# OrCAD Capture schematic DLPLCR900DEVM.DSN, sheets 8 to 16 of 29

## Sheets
8 P23-DMD Flex Connector: size A3
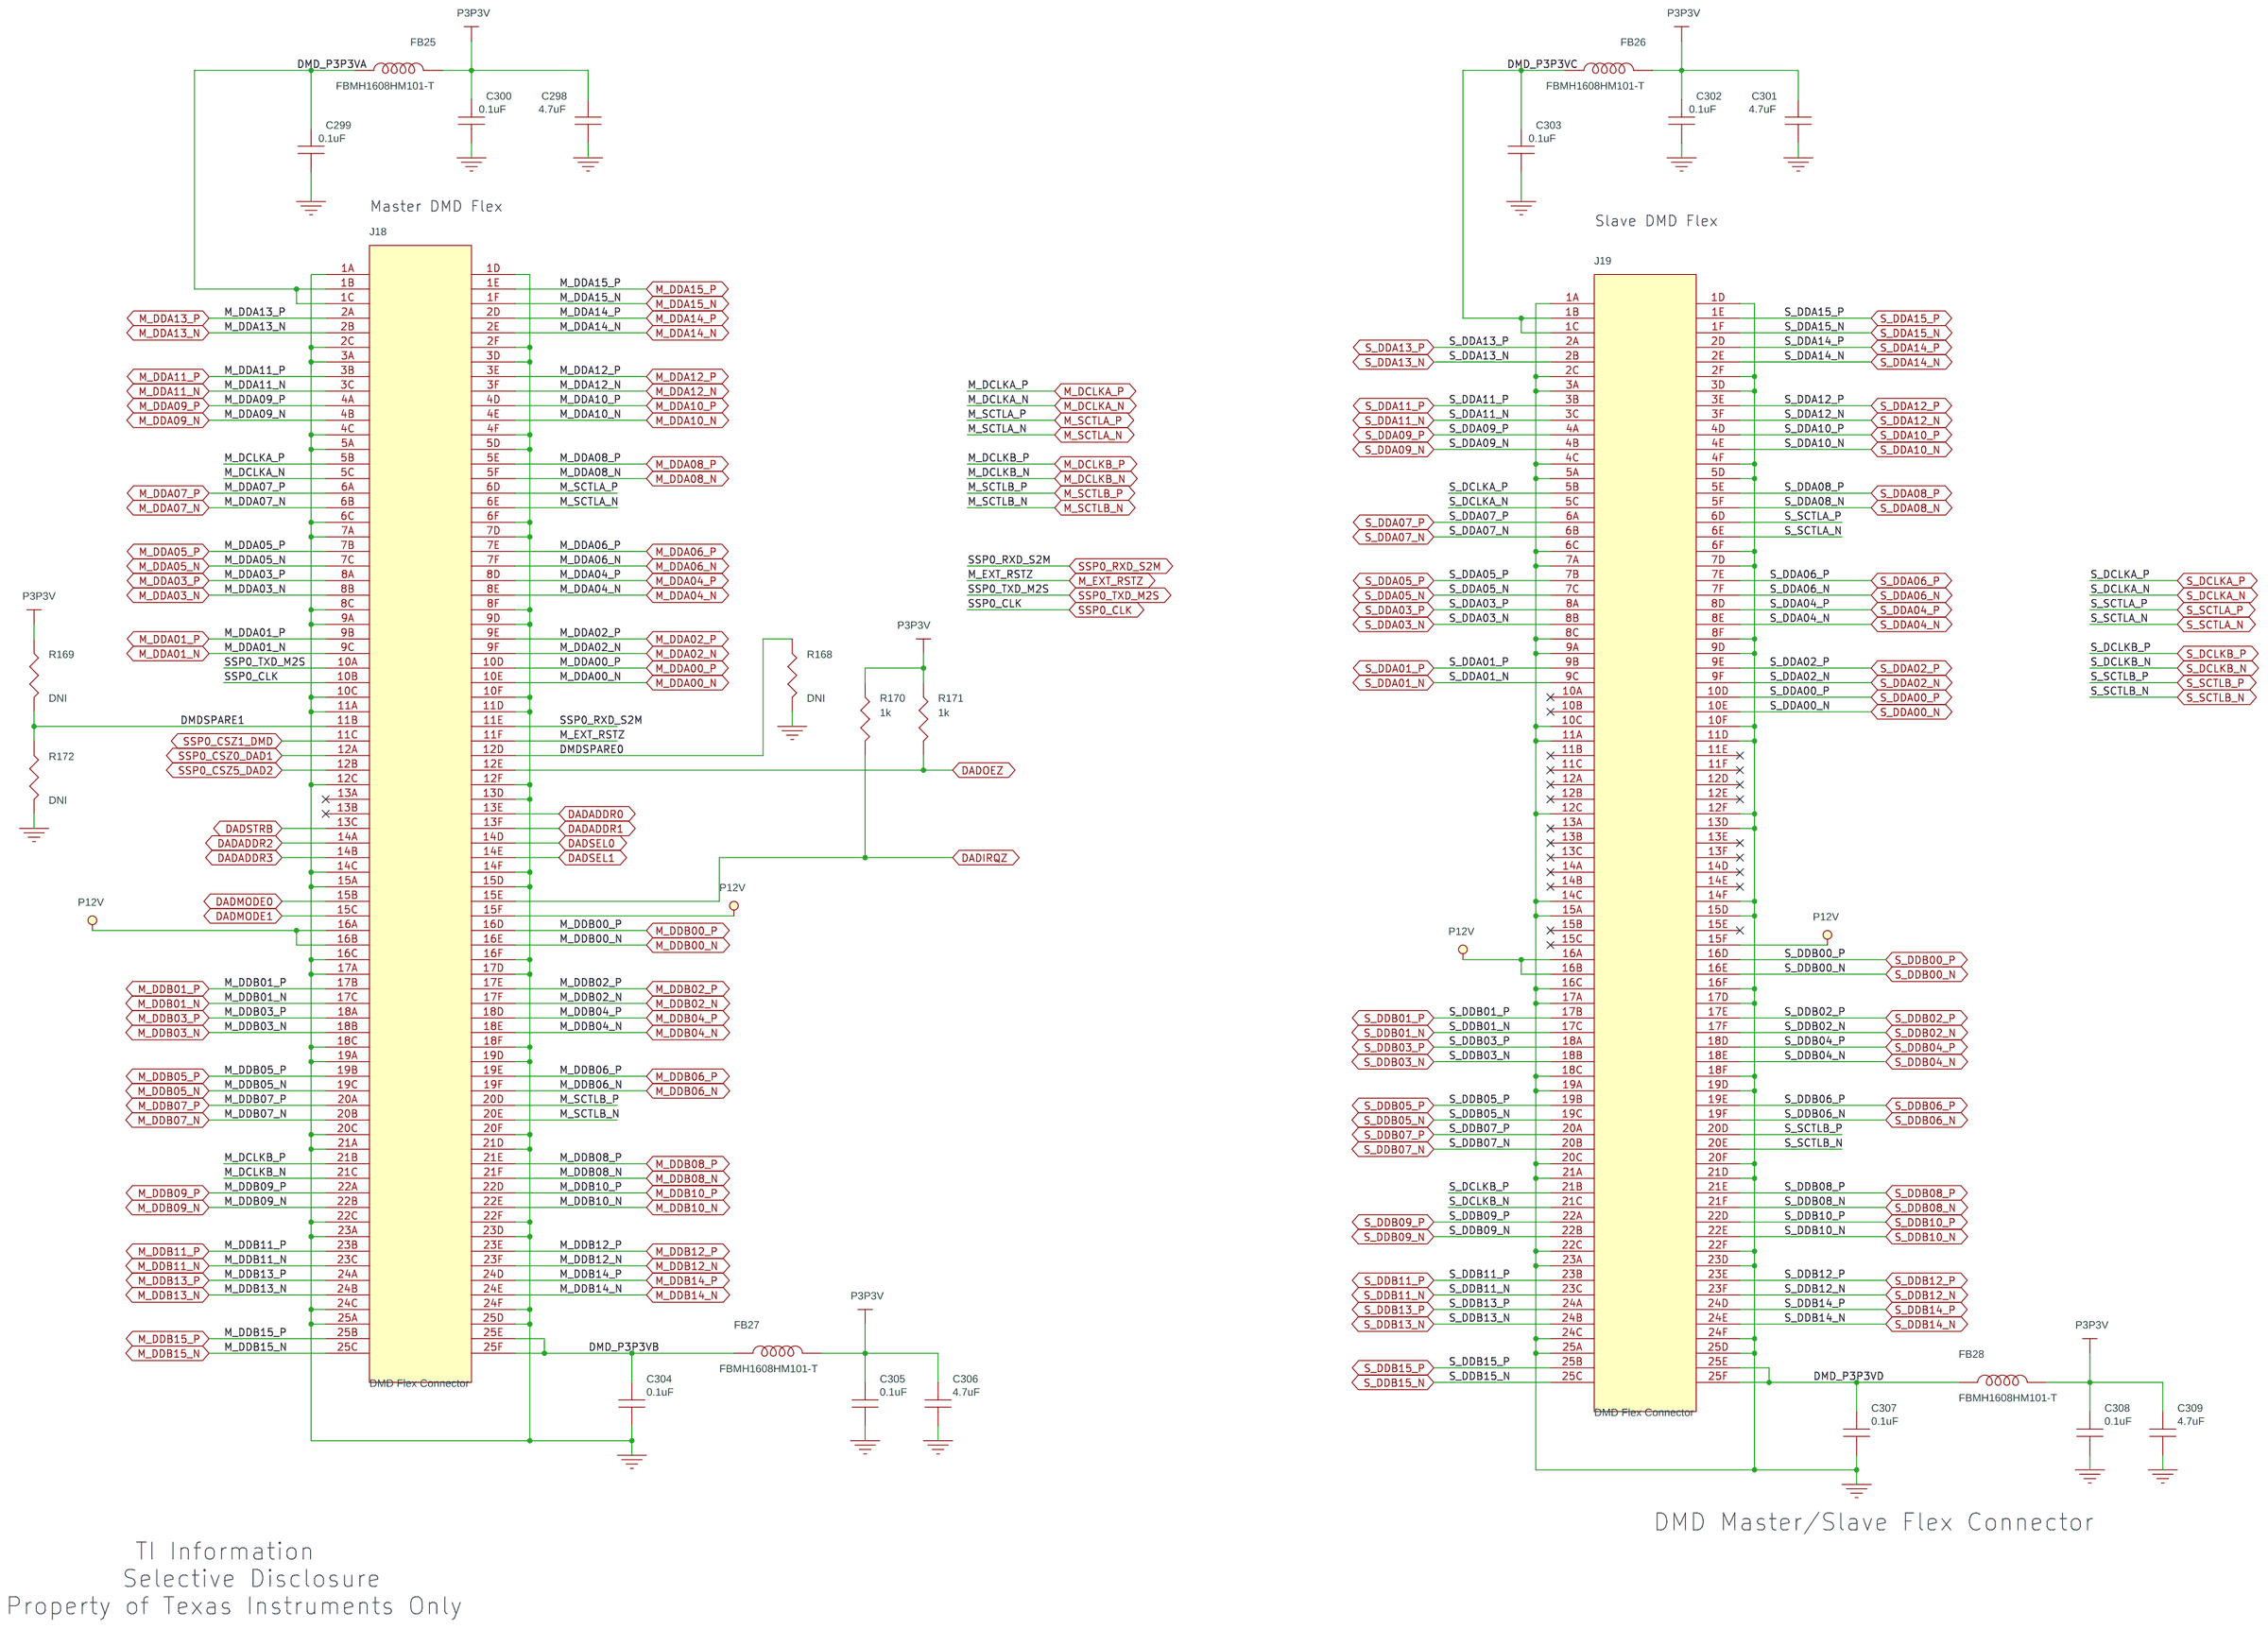
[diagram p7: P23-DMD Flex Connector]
9 P20-Slave Ext Flash Intf: size A3
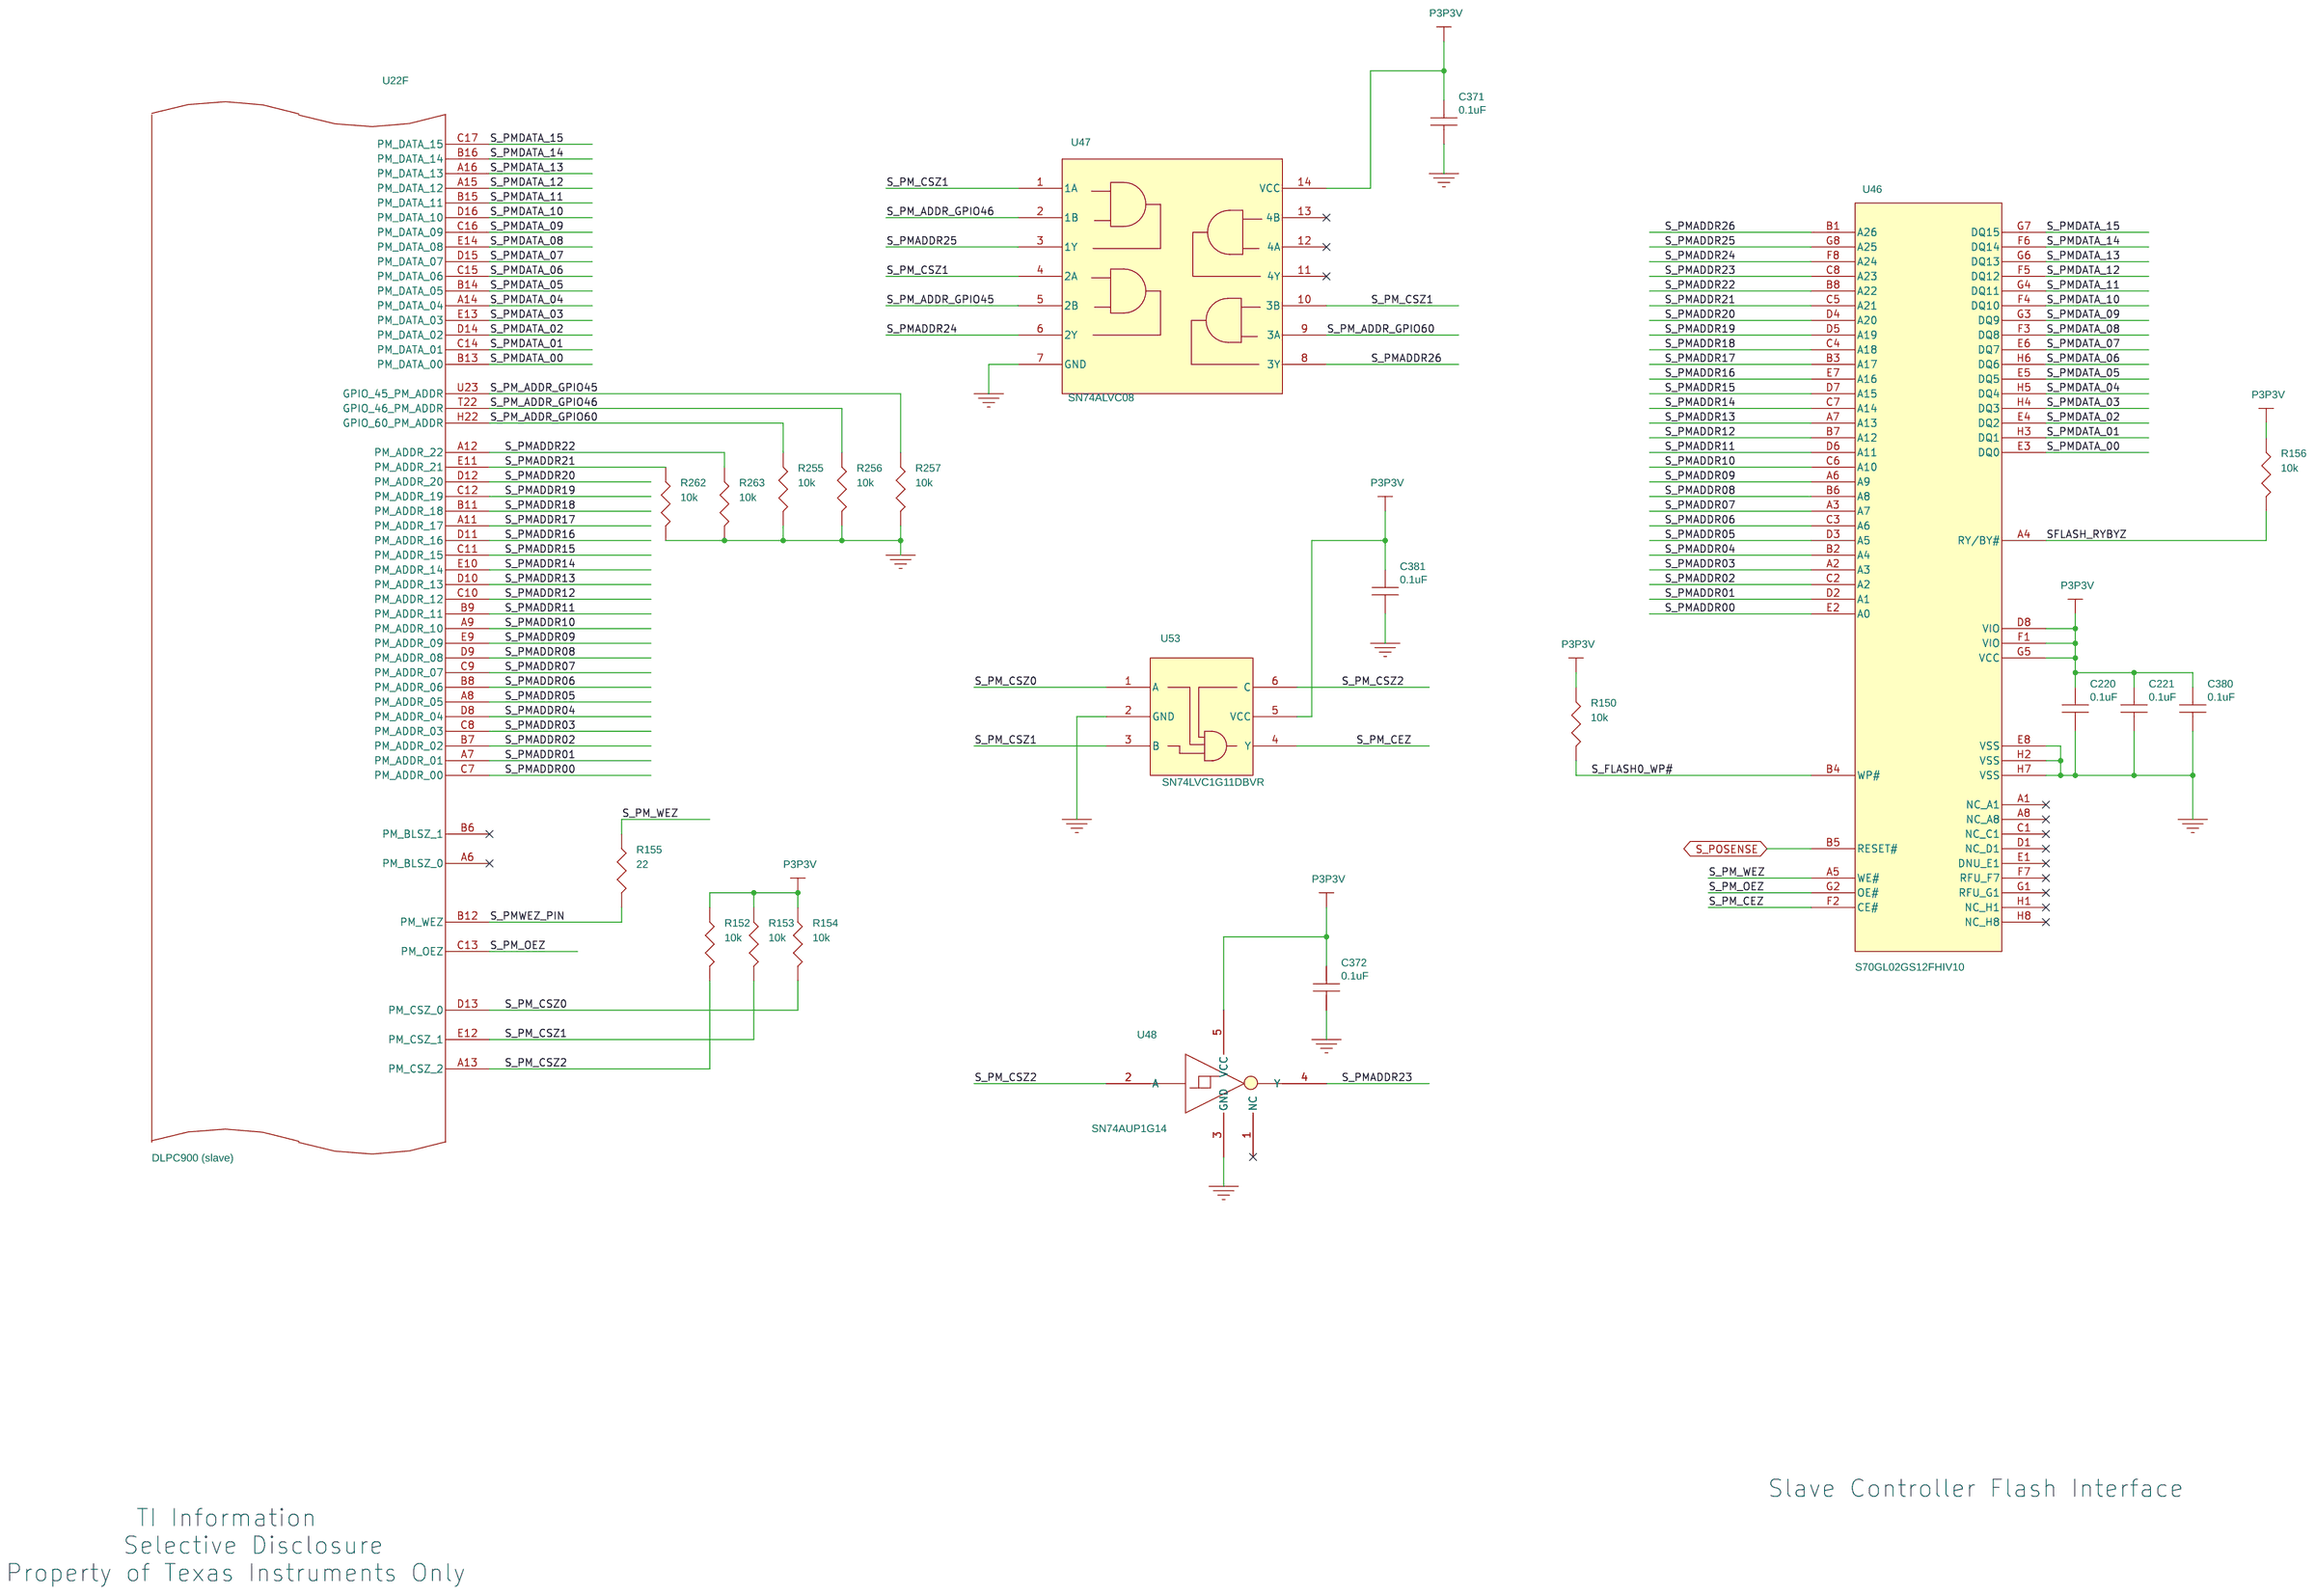
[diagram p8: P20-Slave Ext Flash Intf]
10 P21-Slave GPIOs: size A3
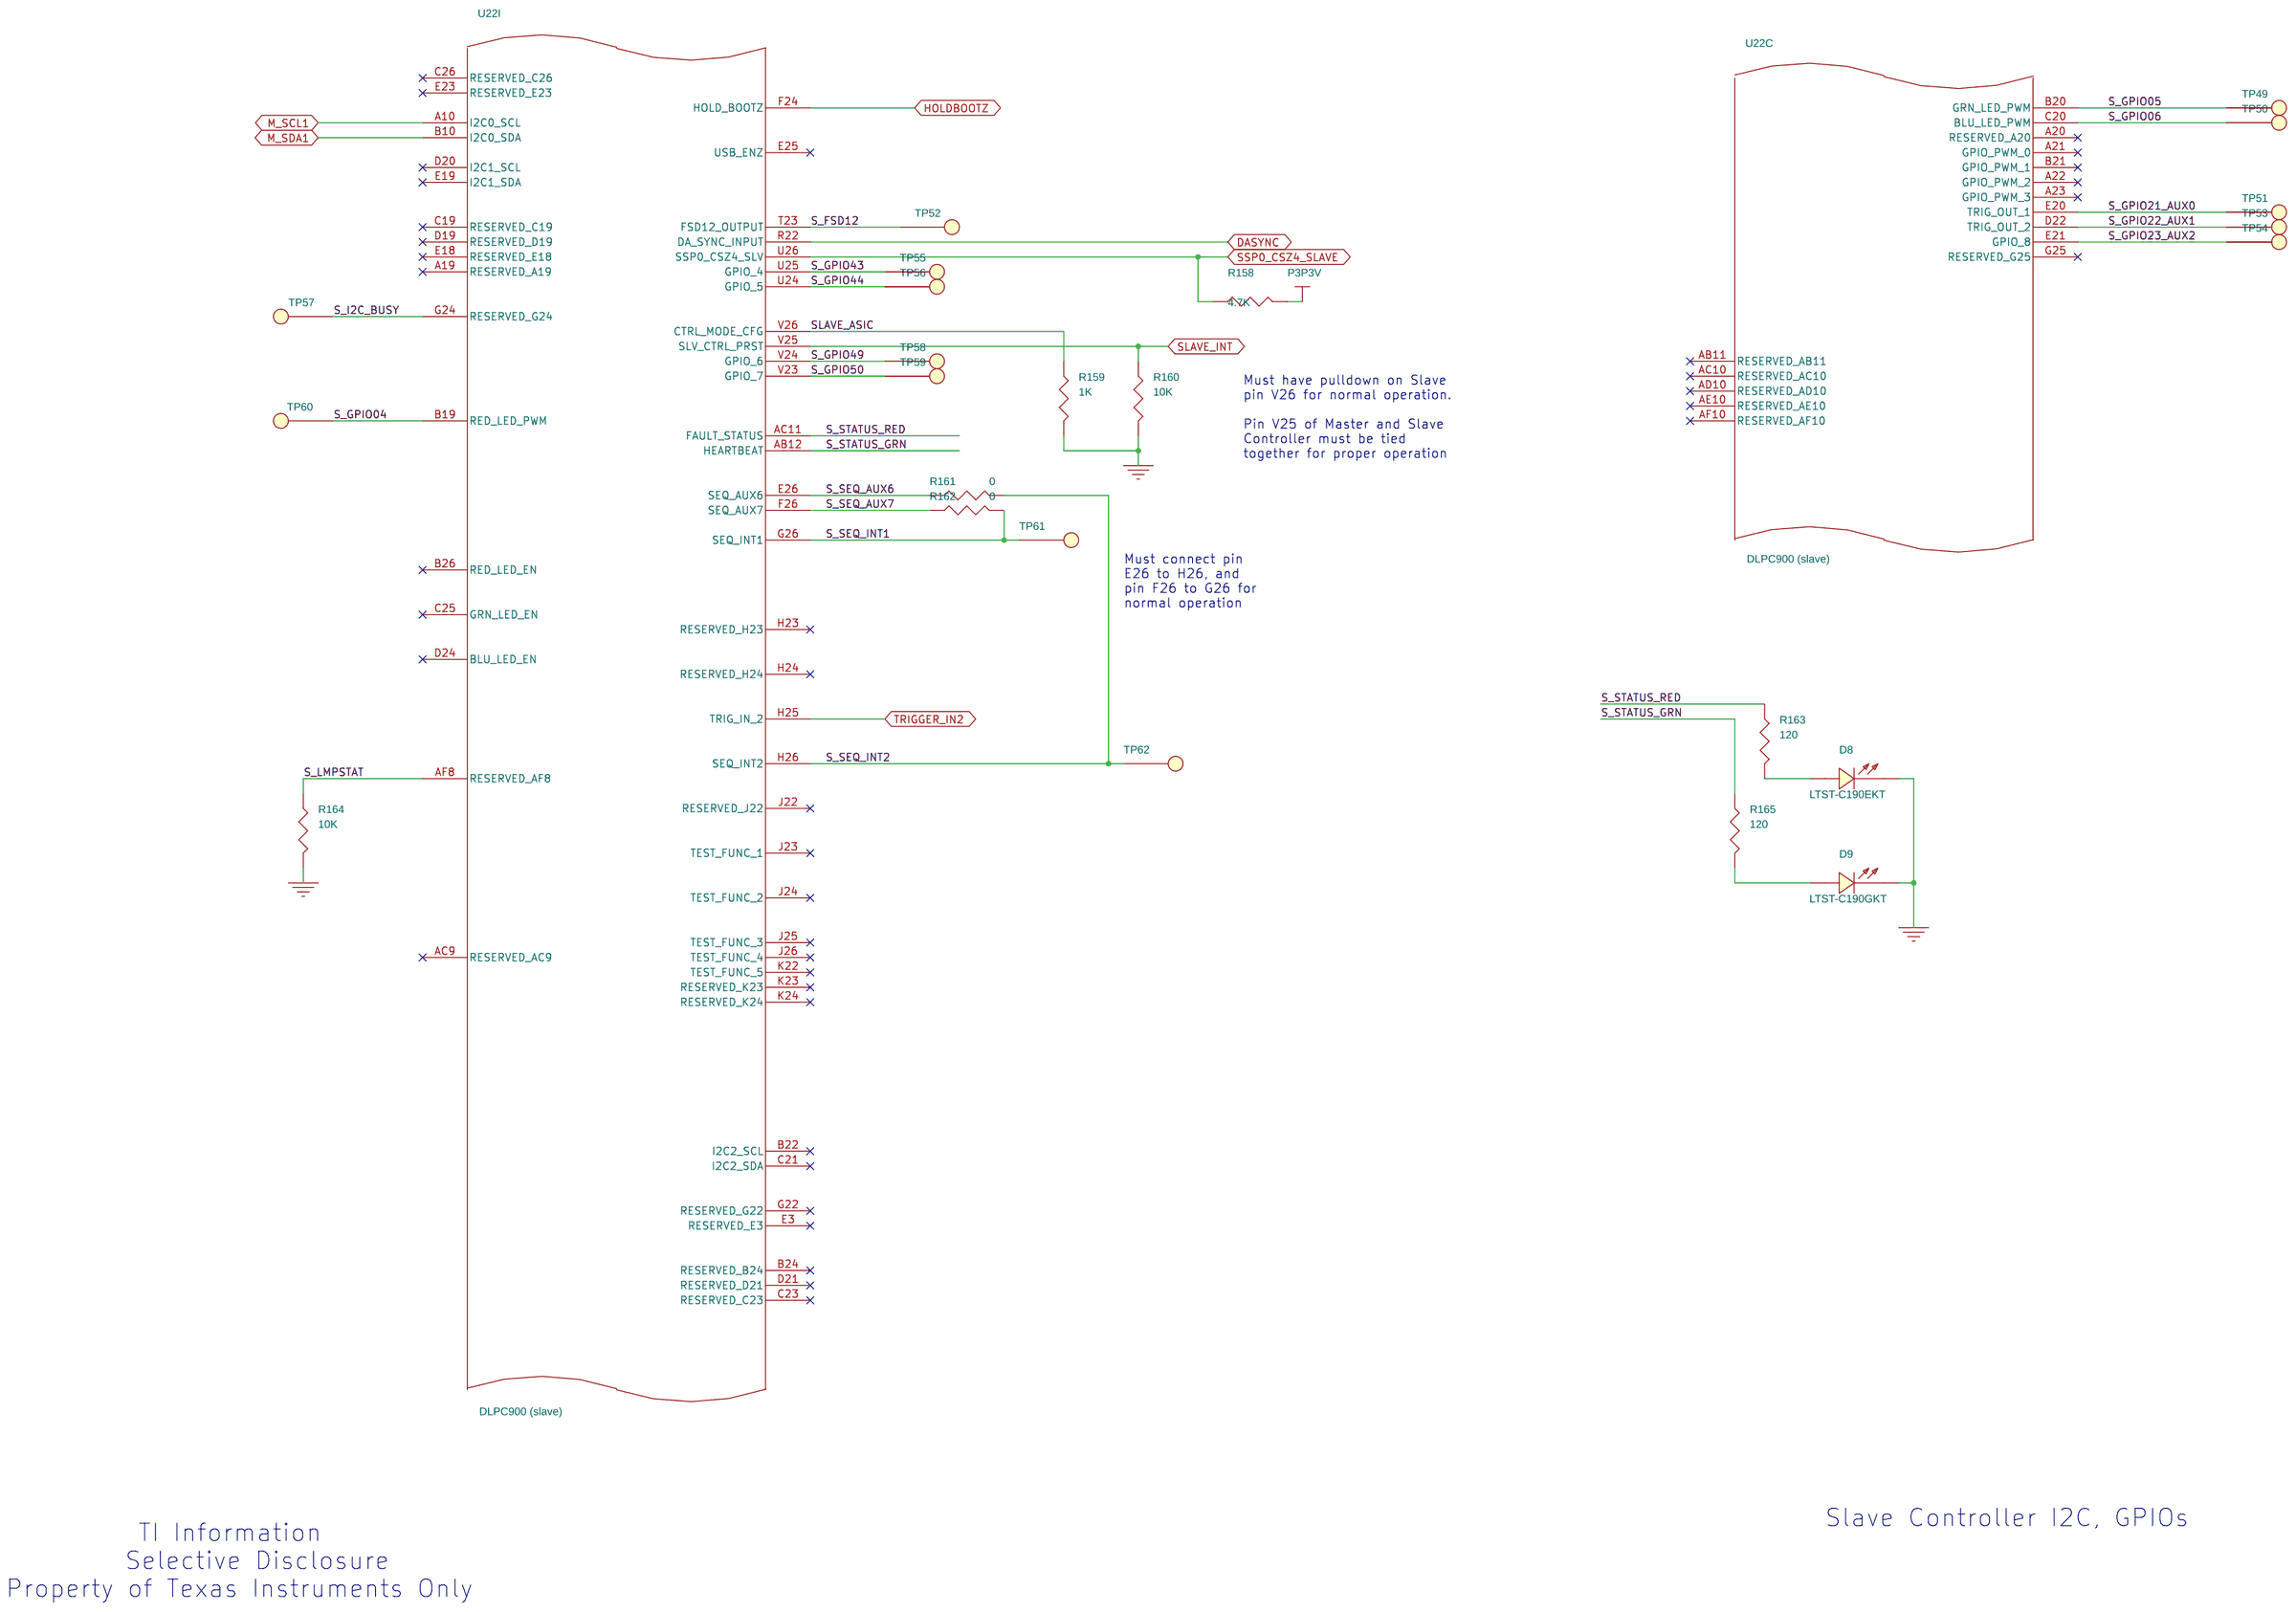
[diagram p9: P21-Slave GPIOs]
11 P19-Slave JTAG Osc Rst SSP: size A3
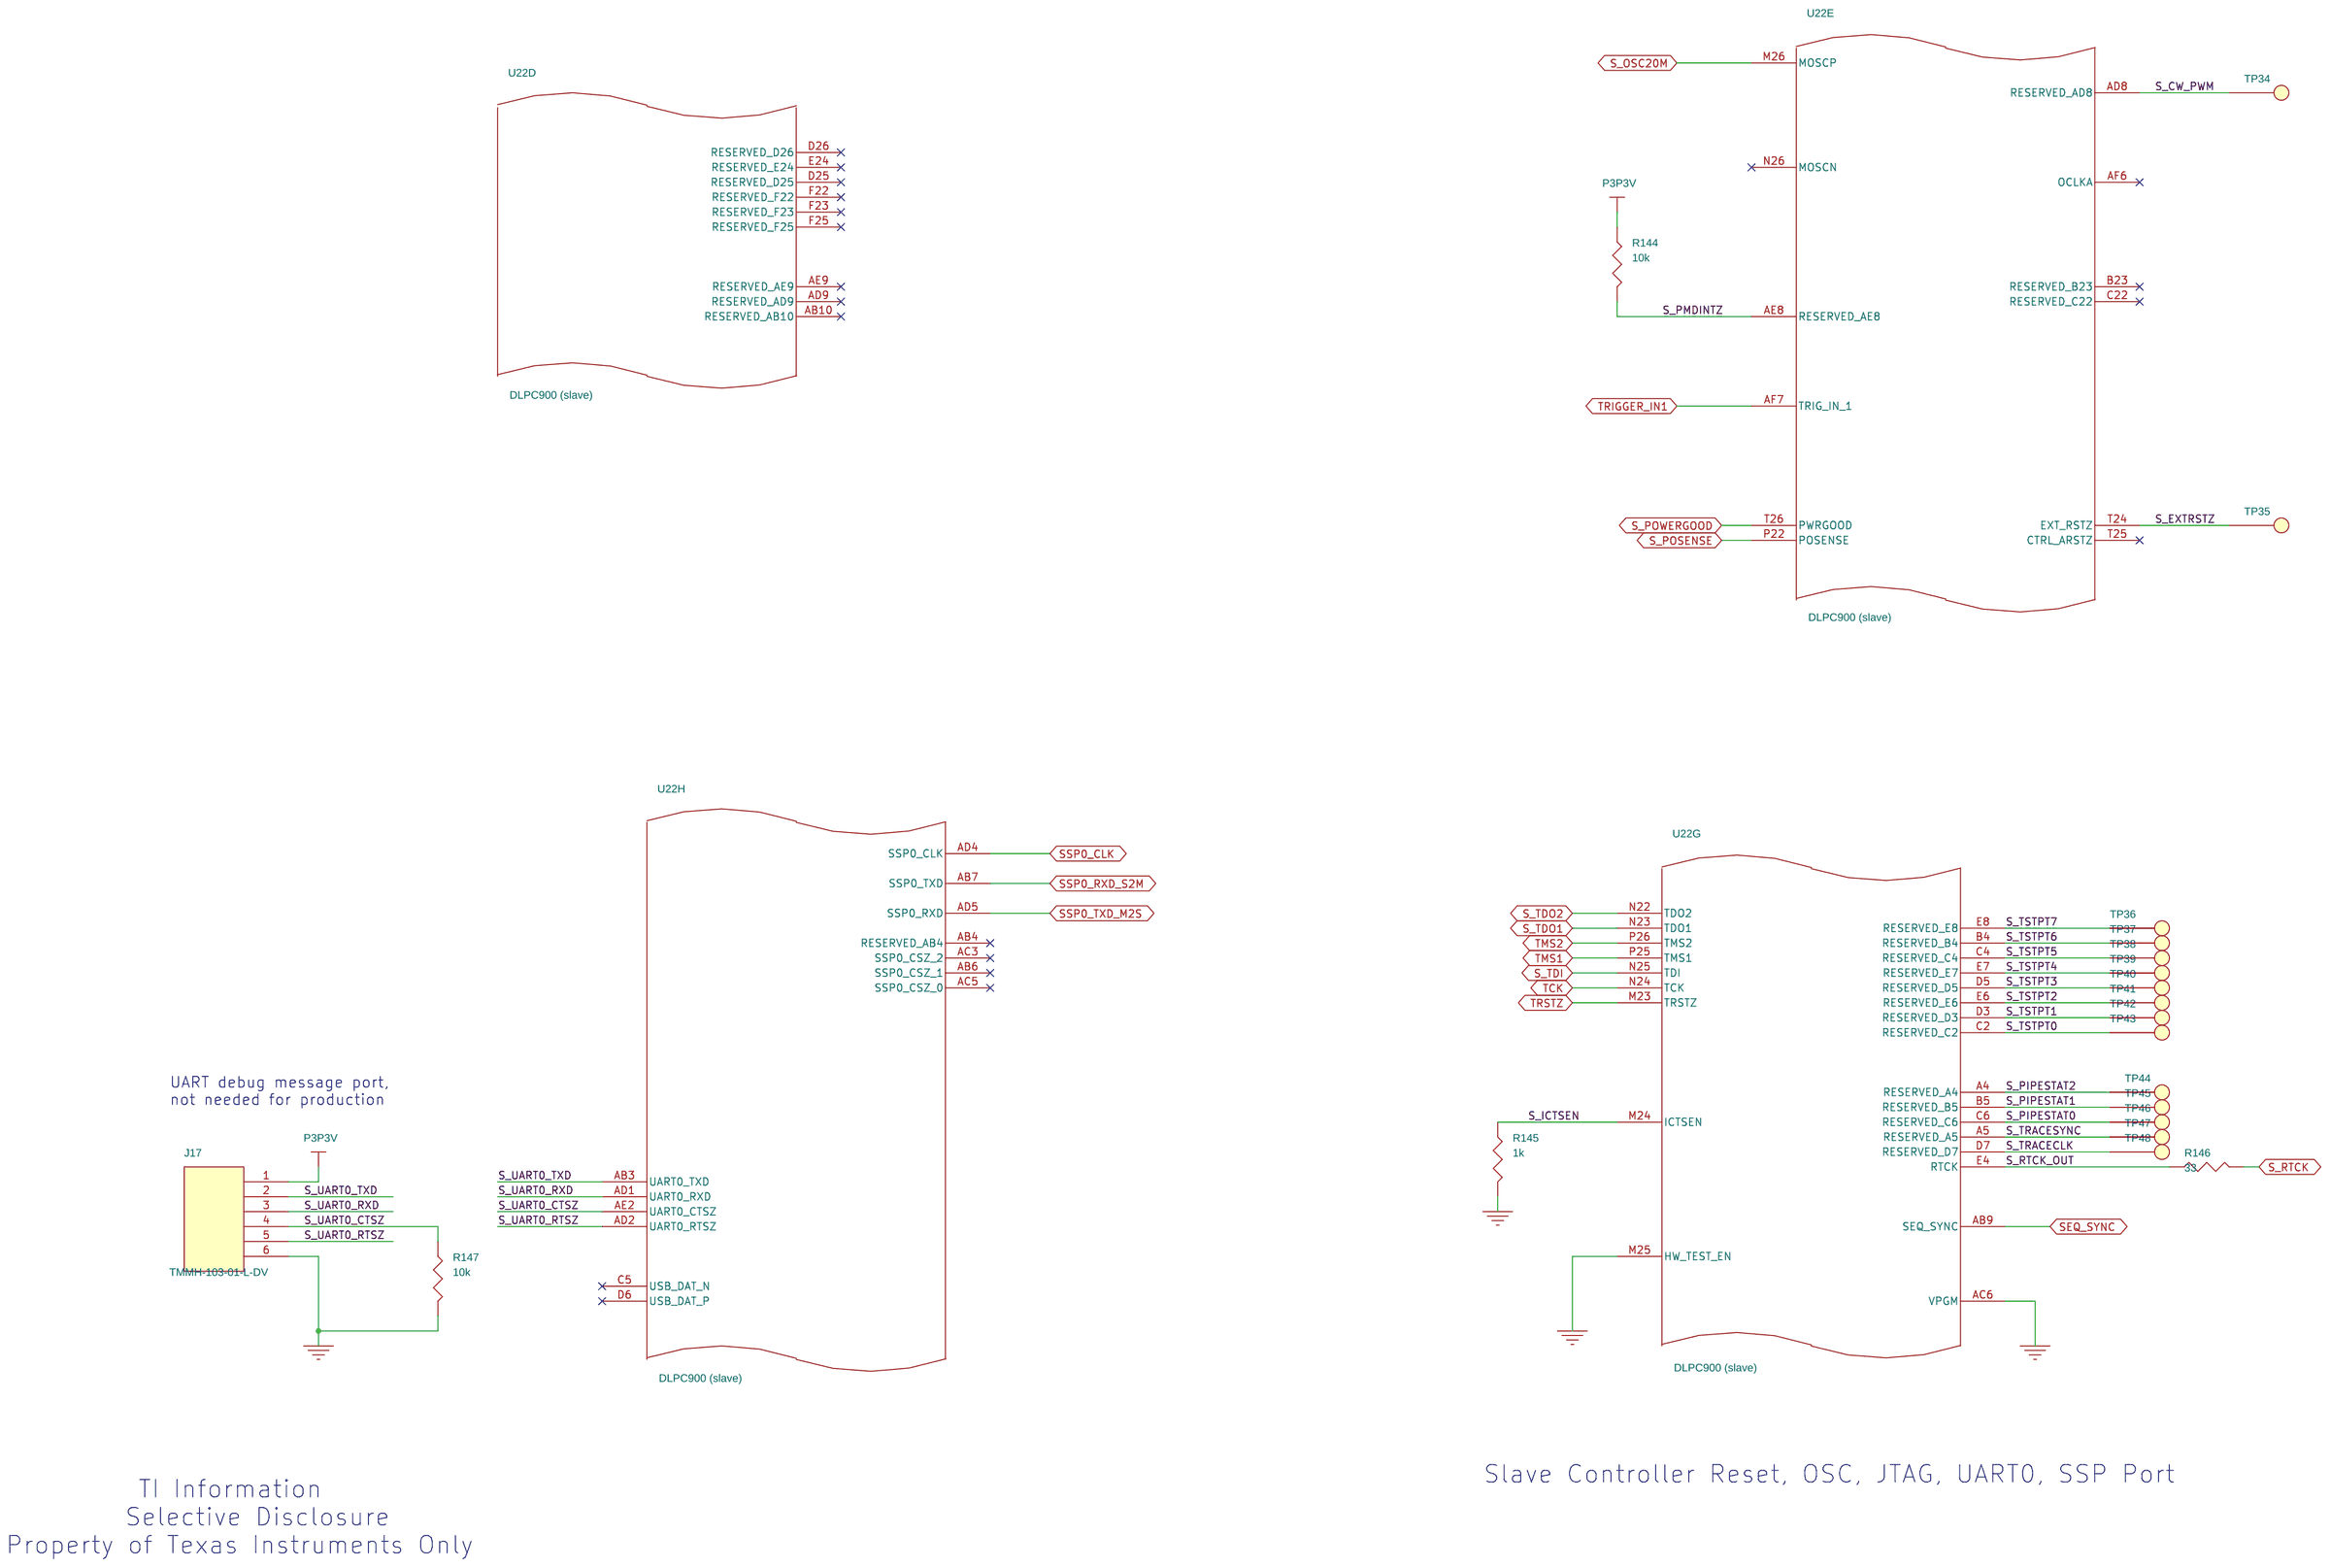
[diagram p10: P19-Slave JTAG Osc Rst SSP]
12 P18-Slave Vid DMD io: size A3
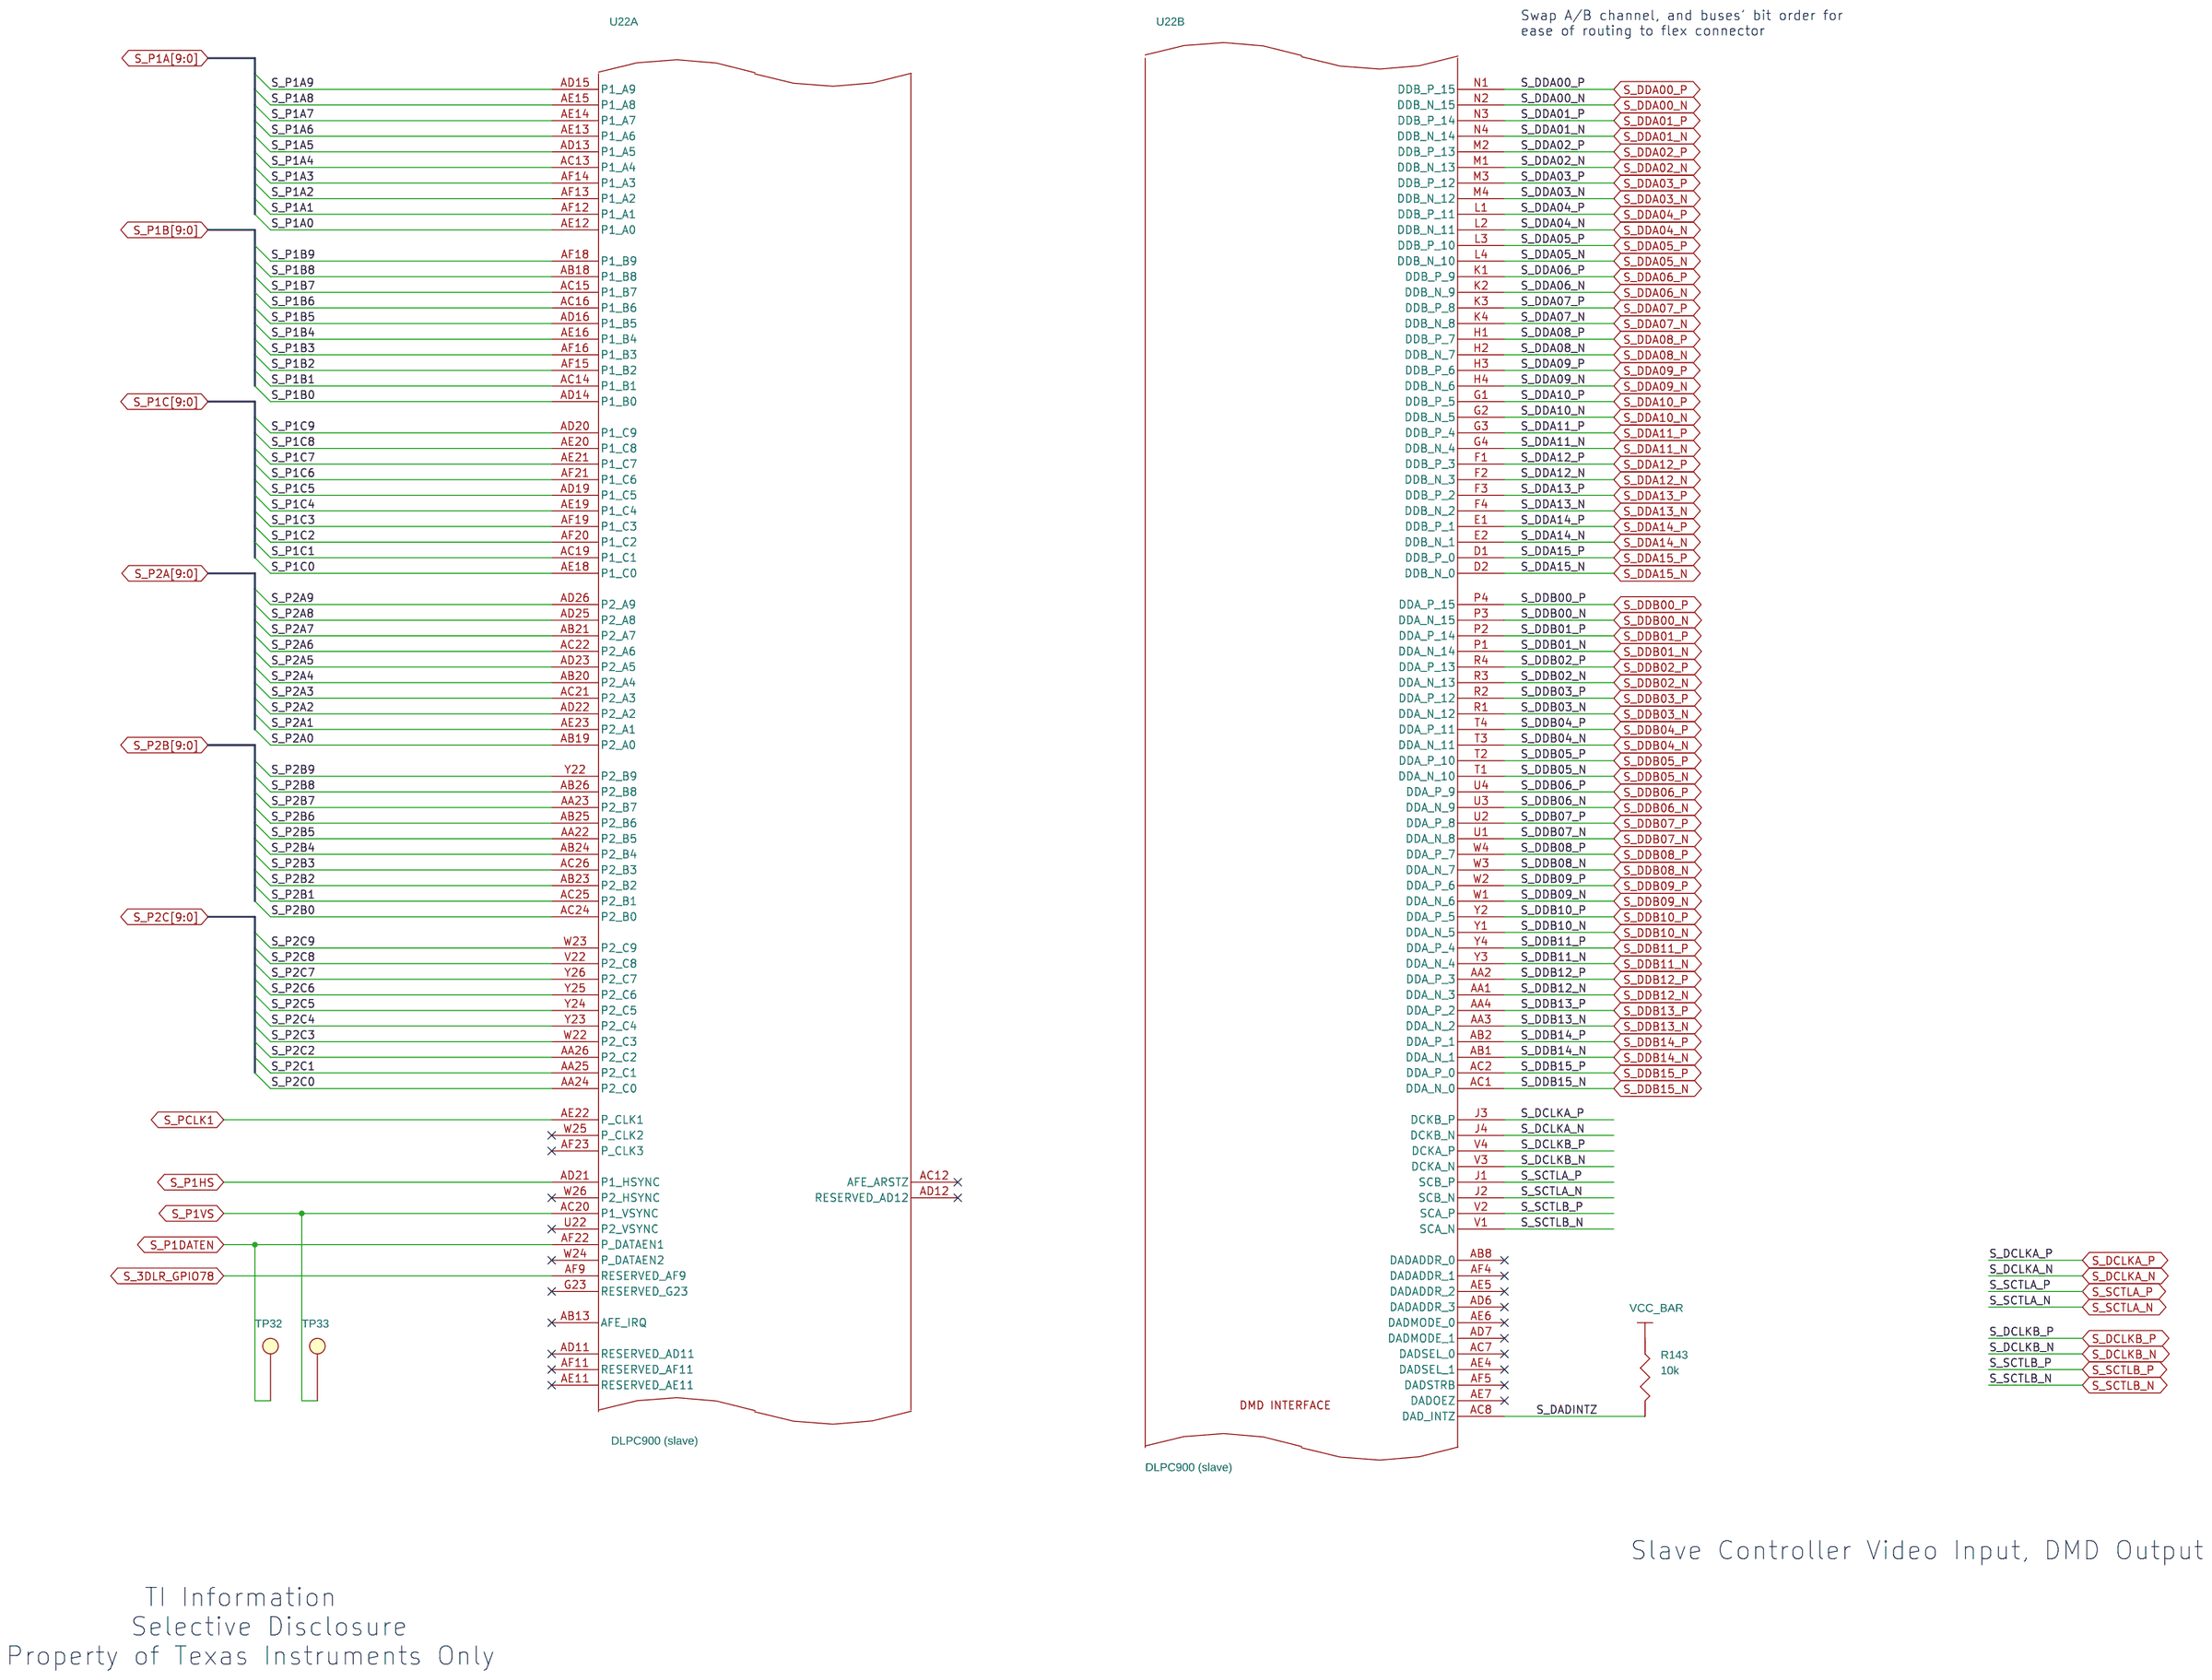
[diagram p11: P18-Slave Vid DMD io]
13 P26-Inout Trigger, LED Driver: size A3
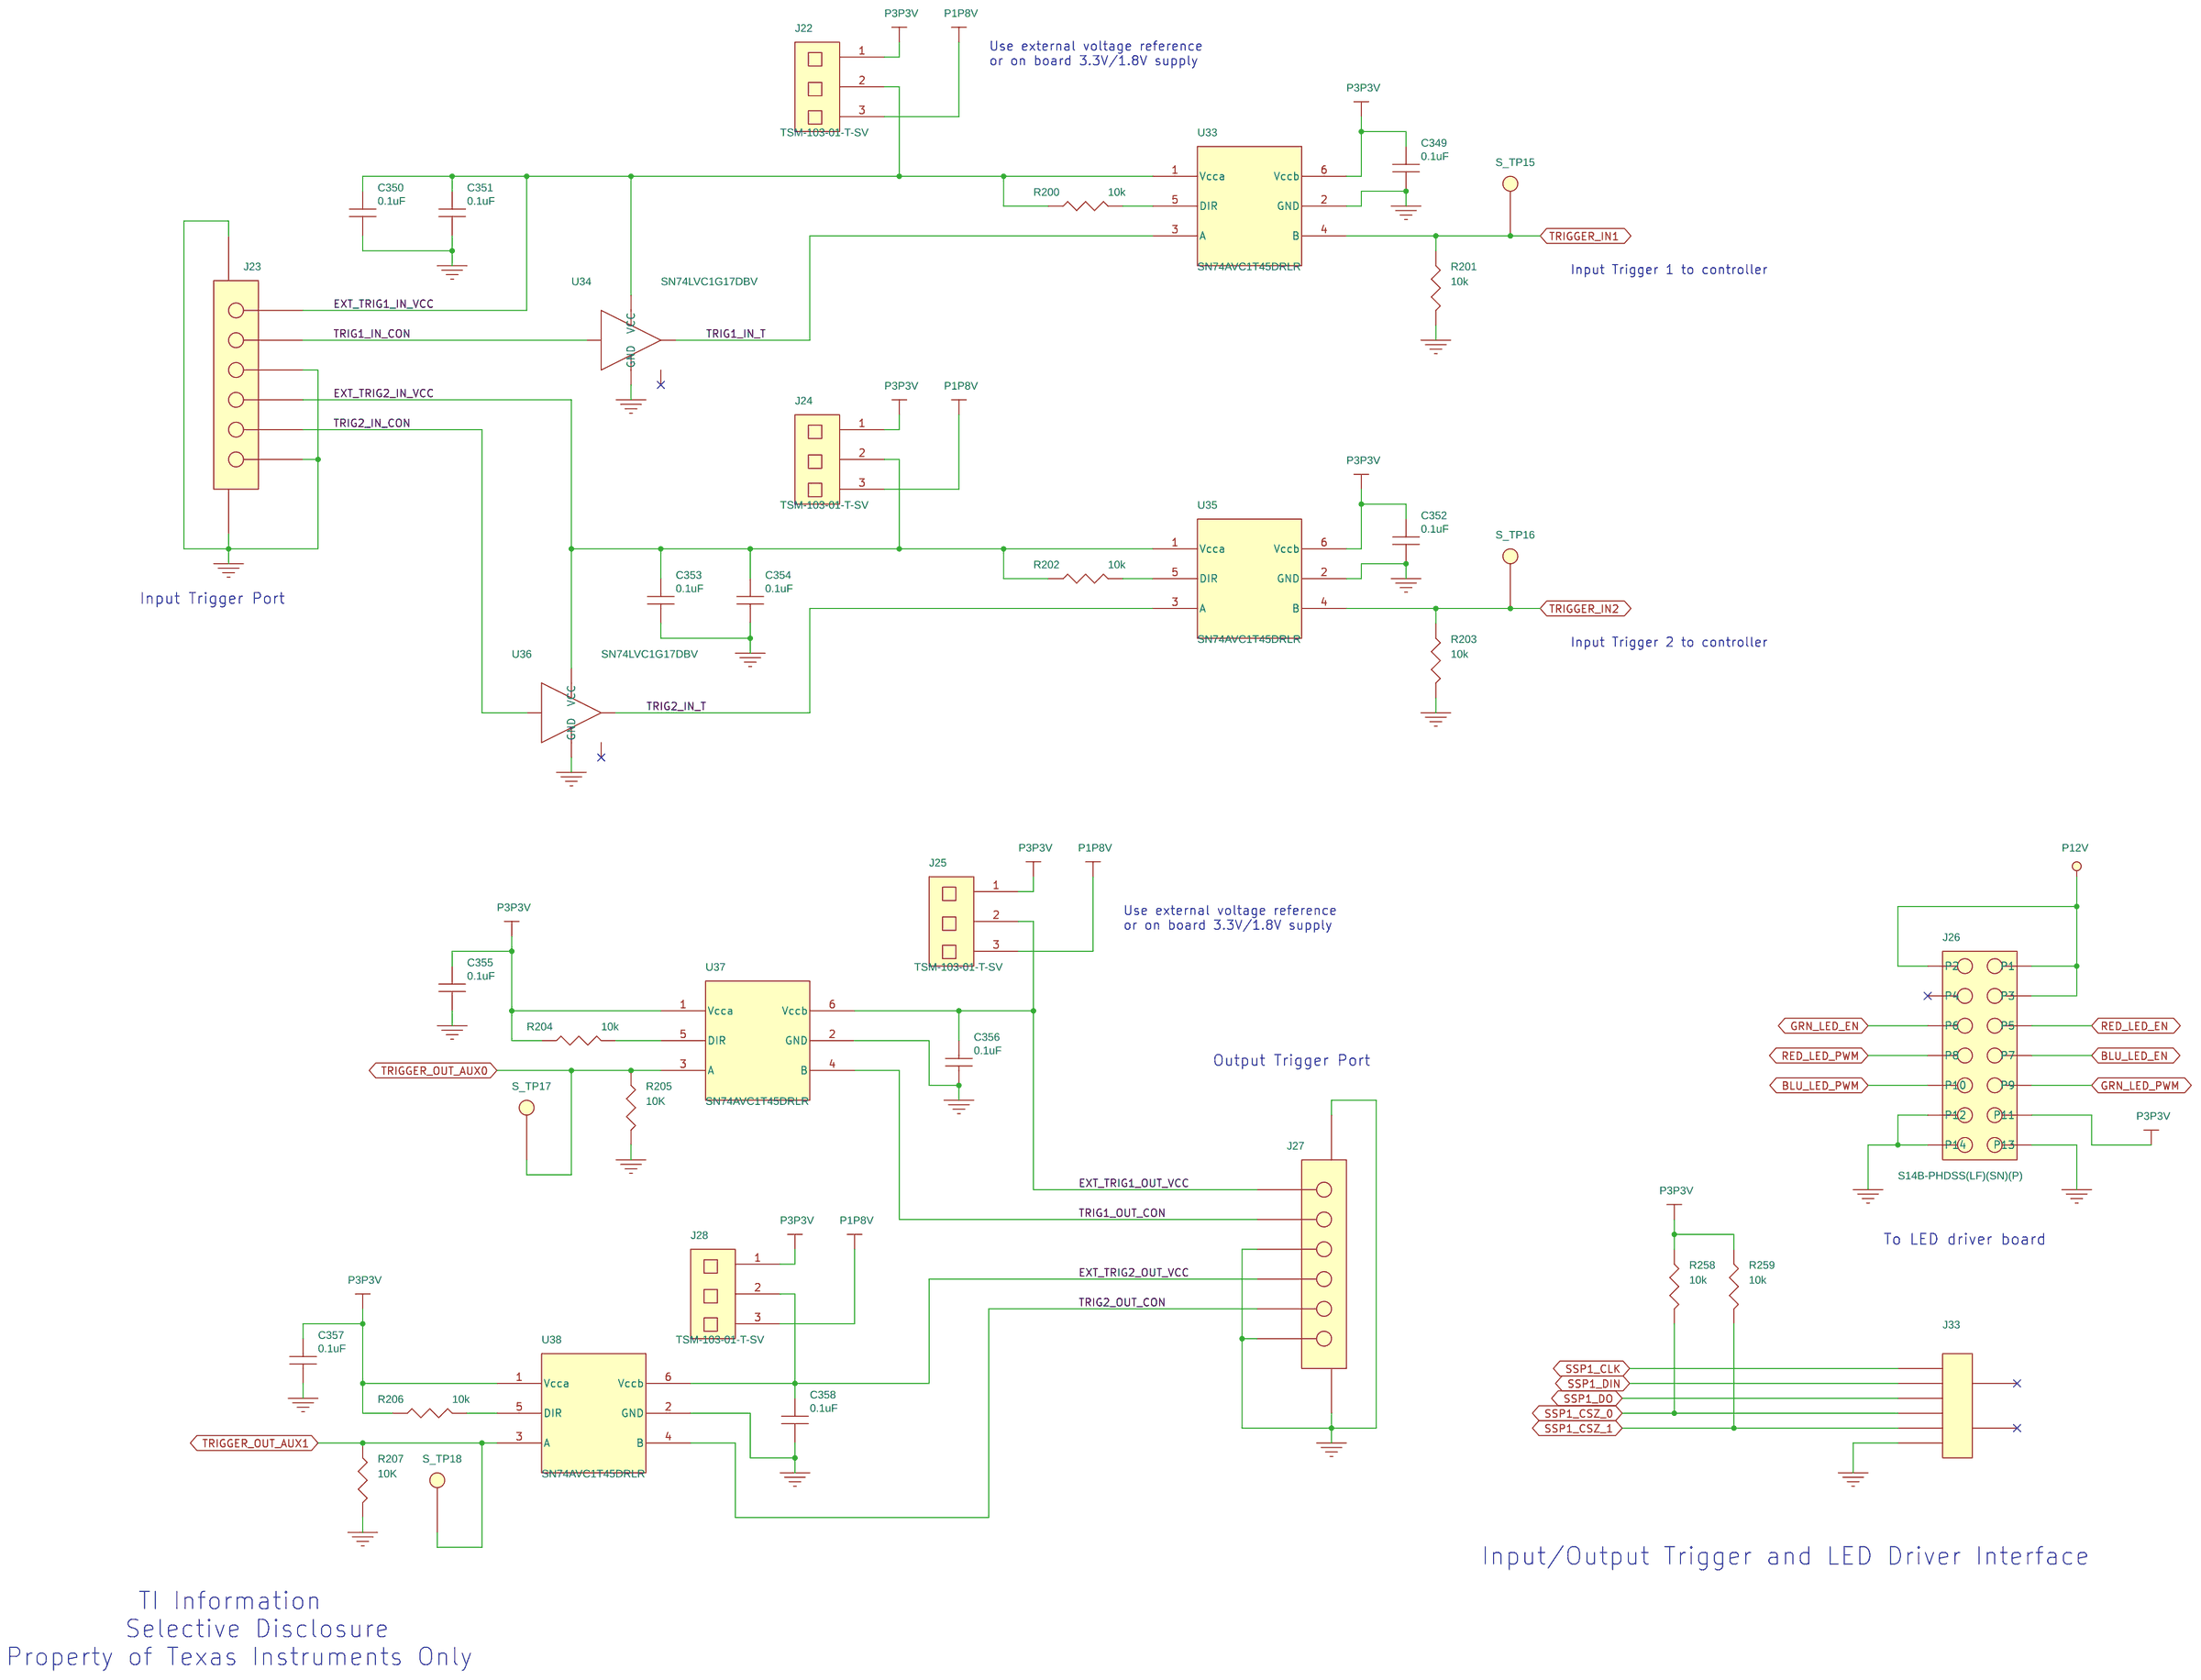
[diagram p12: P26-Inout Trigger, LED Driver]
14 P27-Gen pwrgood posense clk: size A3
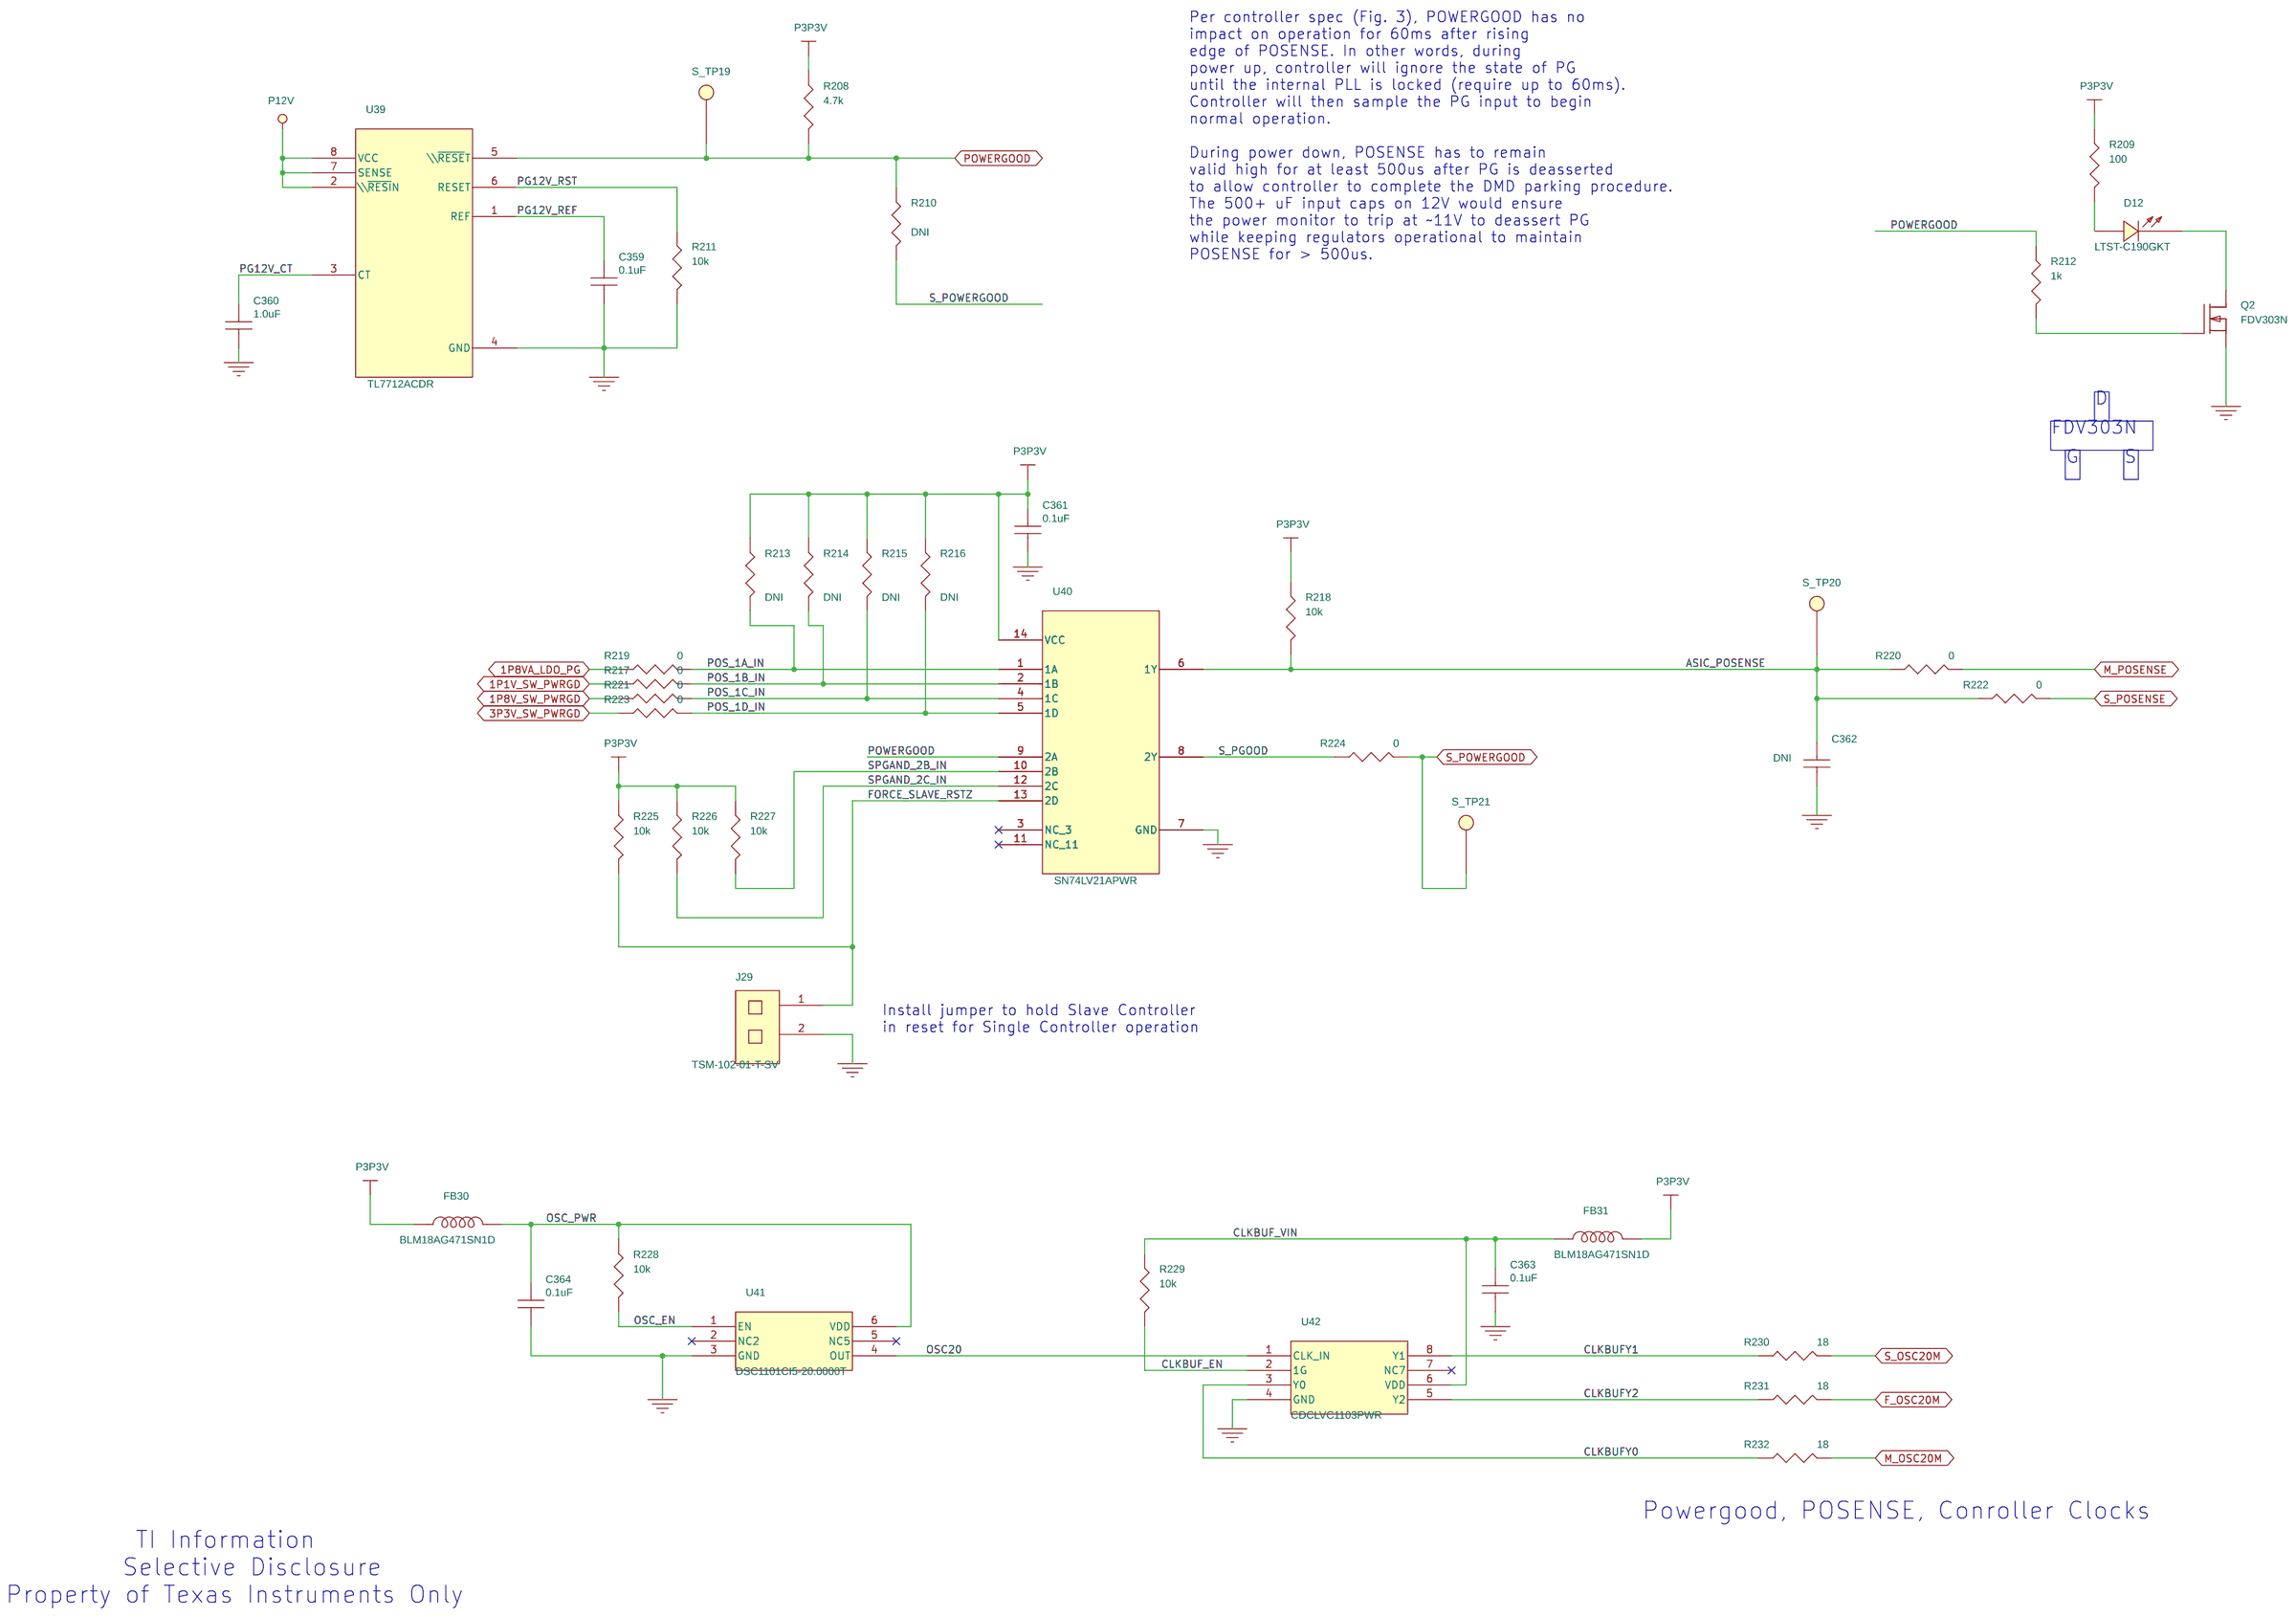
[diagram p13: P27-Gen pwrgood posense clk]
15 P16-Master I2C Trig GPIO: size A3
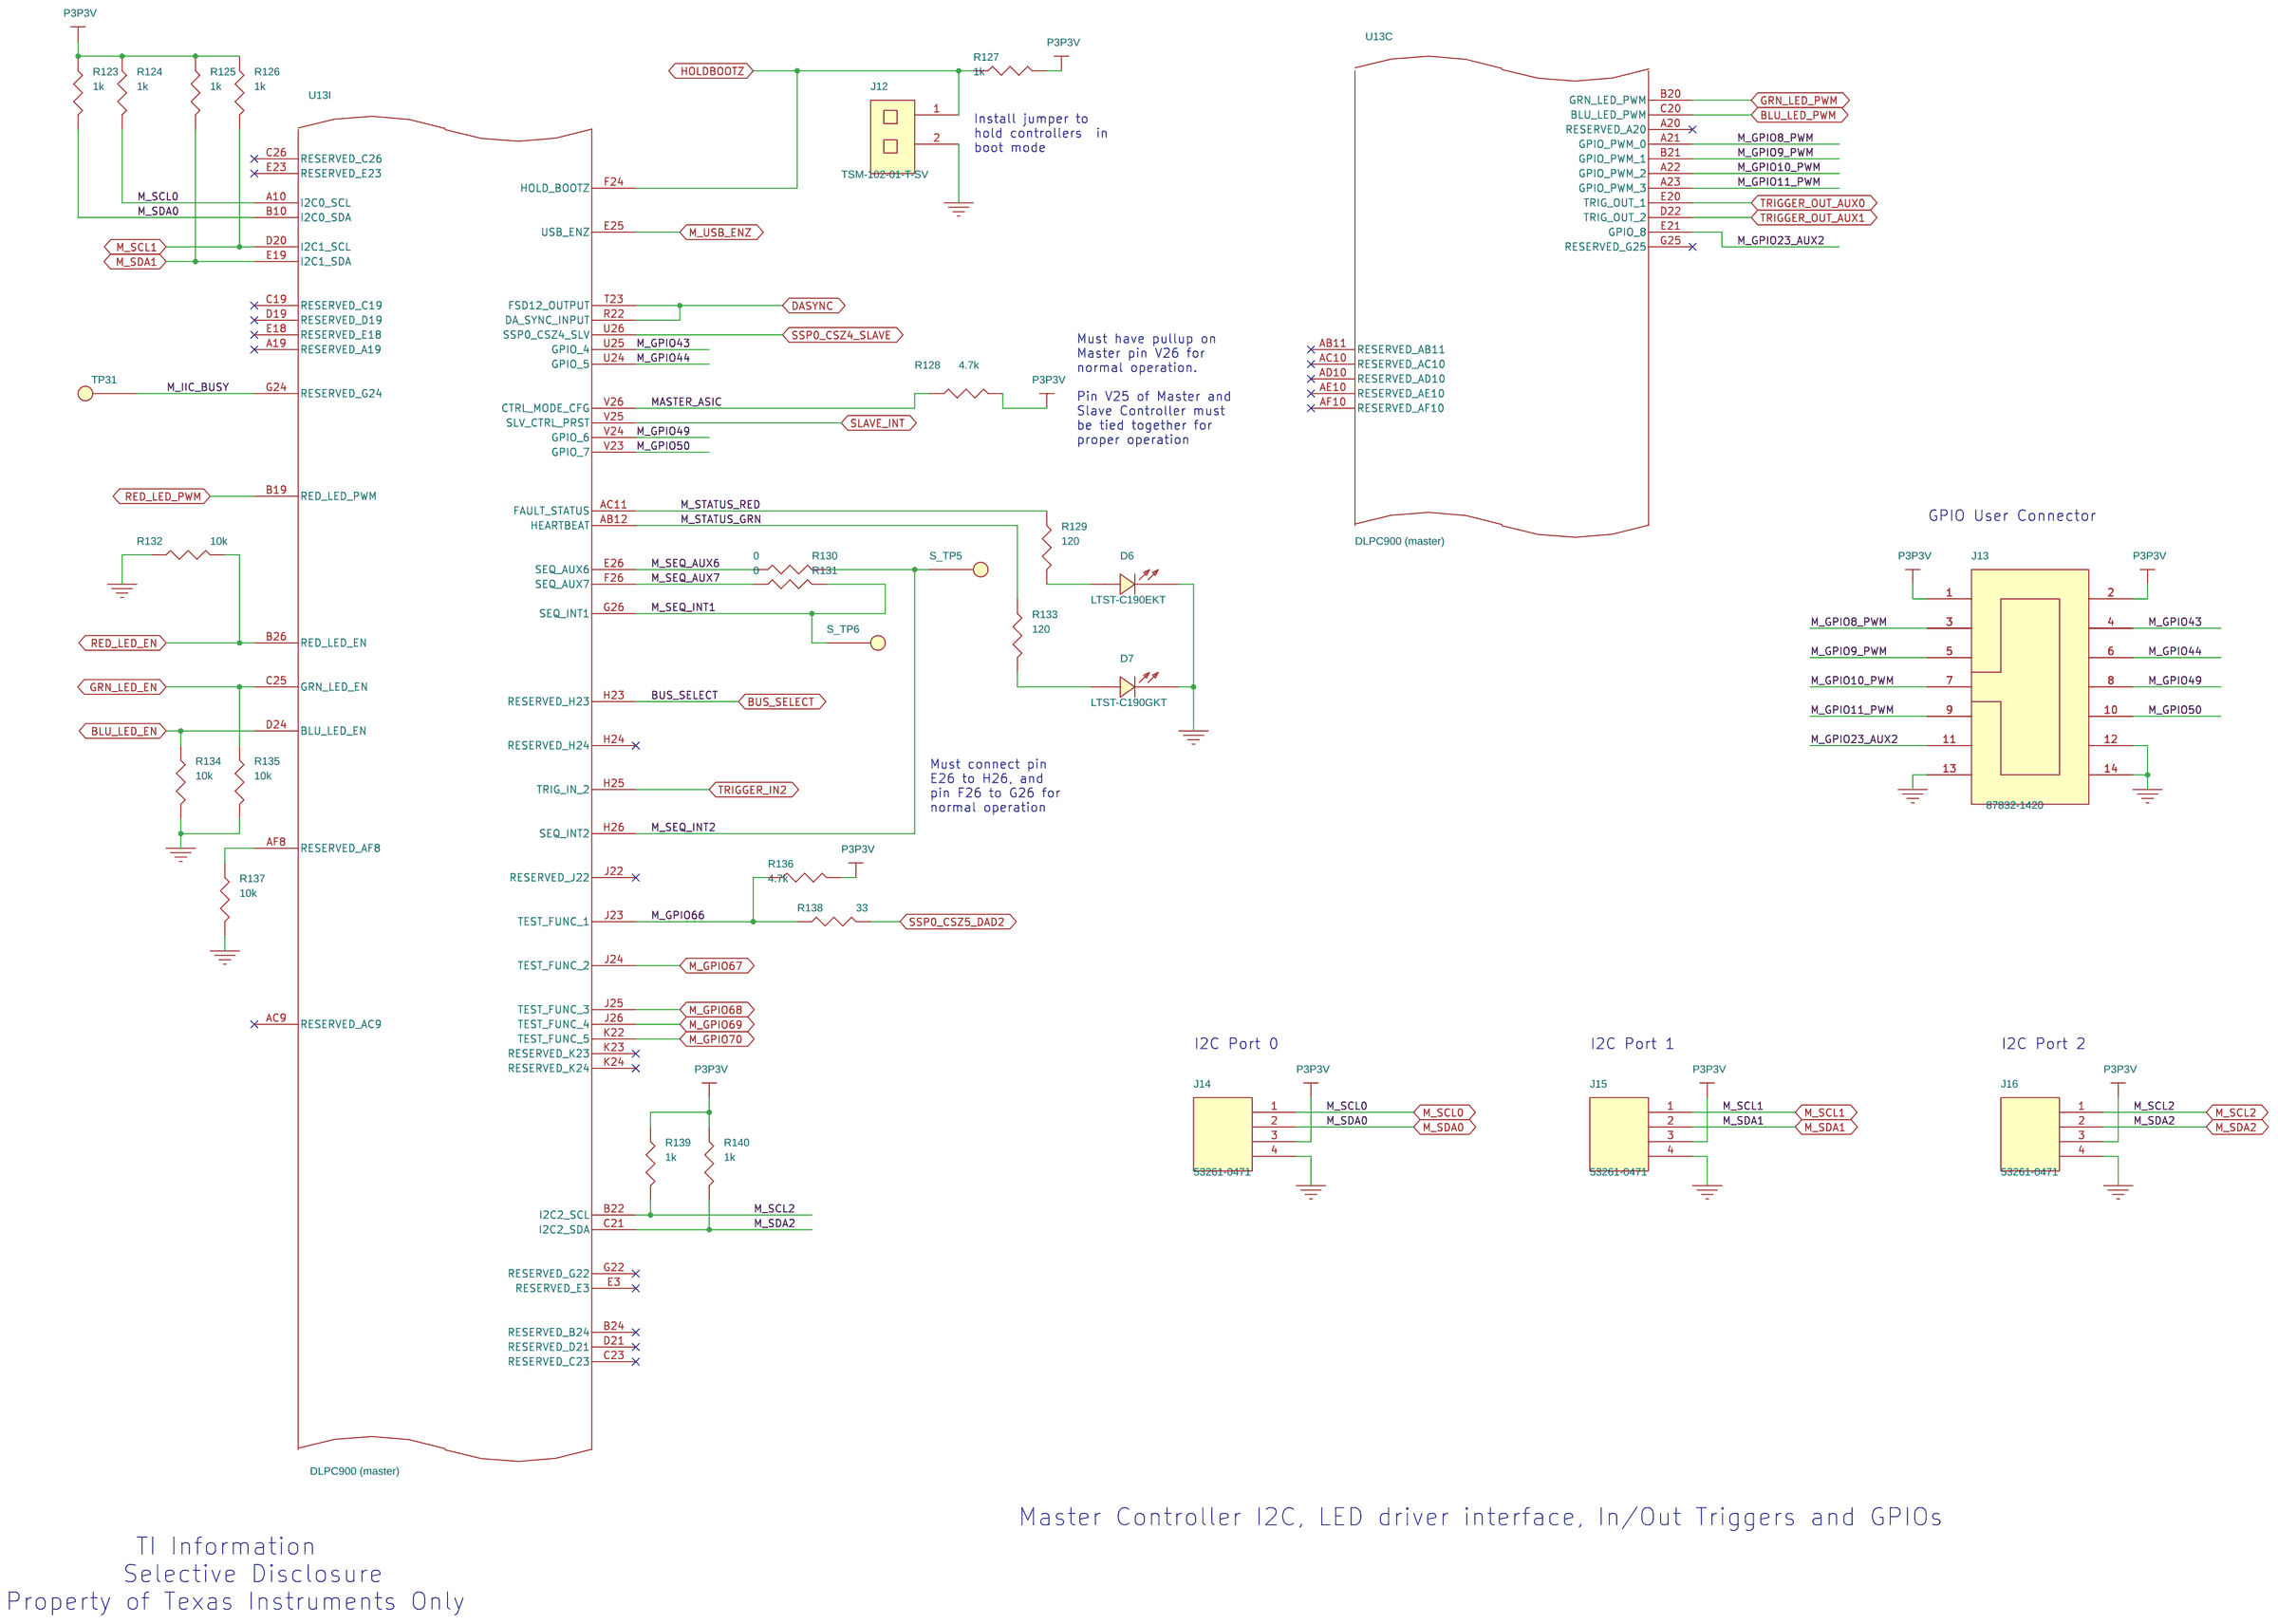
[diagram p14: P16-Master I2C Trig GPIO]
16 P15-Master ICE JTAG: size A3
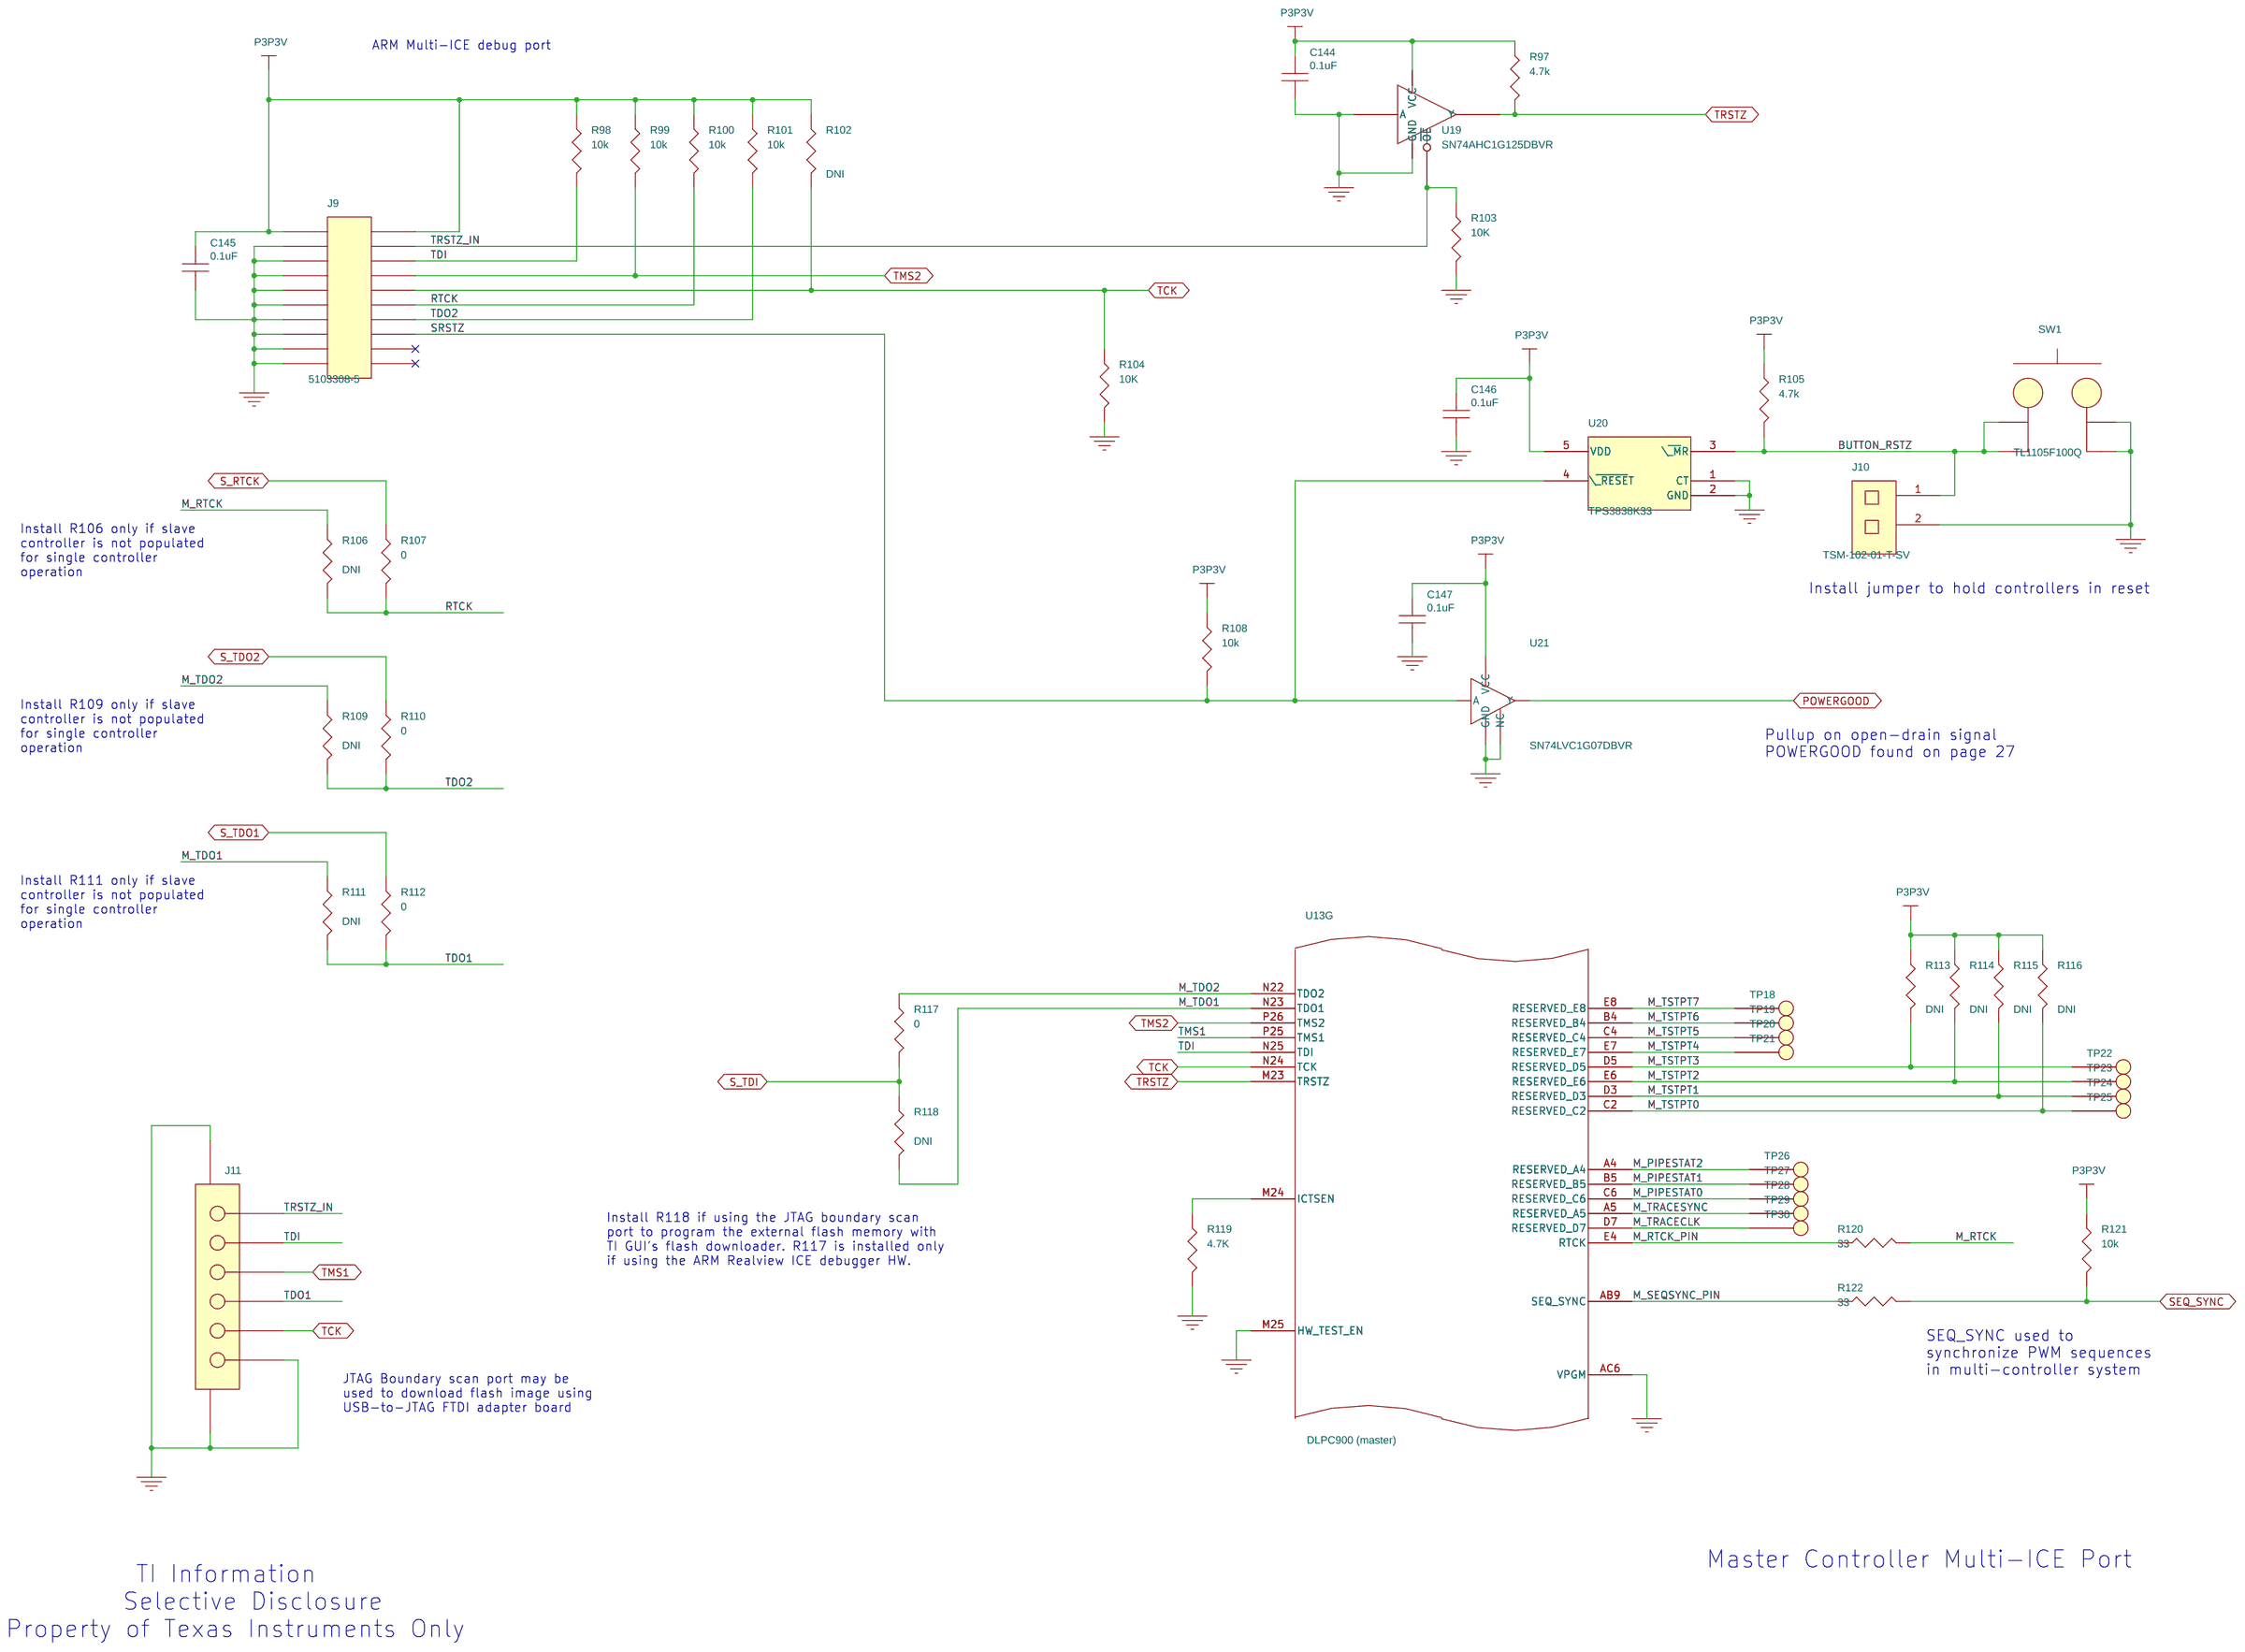
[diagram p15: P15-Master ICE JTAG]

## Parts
sheet P14-Master Ext Flash Intf
U13  DLPC900 (master)  [516BGA]  (sections A,B,C,D,E,F,G,H,I,J)
sheet P15-Master ICE JTAG
C144  0.1uF  [0402]
C145  0.1uF  [0402]
C146  0.1uF  [0402]
C147  0.1uF  [0402]
J9  5103308-5  [2x10Pos]
J10  TSM-102-01-T-SV  [2POS-2p54mm]
J11  0532610671  [6pos_1p25mm]
R97  4.7k  [0402]
R98  10k  [0402]
R99  10k  [0402]
R100  10k  [0402]
R101  10k  [0402]
R102  DNI  [0402]
R103  10K  [0402]
R104  10K  [0402]
R105  4.7k  [0402]
R106  DNI  [0603]
R107  0  [0603]
R108  10k  [0402]
R109  DNI  [0603]
R110  0  [0603]
R111  DNI  [0603]
R112  0  [0603]
R113  DNI  [0402]
R114  DNI  [0402]
R115  DNI  [0402]
R116  DNI  [0402]
R117  0  [0603]
R118  DNI  [0603]
R119  4.7K  [0402]
R120  33  [0402]
R121  10k  [0402]
R122  33  [0402]
SW1  TL1105F100Q  [6x6mm]
TP18  Testpoint  [24mil-plated]
TP19  Testpoint  [24mil-plated]
TP20  Testpoint  [24mil-plated]
TP21  Testpoint  [24mil-plated]
TP22  Testpoint  [24mil-plated]
TP23  Testpoint  [24mil-plated]
TP24  Testpoint  [24mil-plated]
TP25  Testpoint  [24mil-plated]
TP26  Testpoint  [24mil-plated]
TP27  Testpoint  [24mil-plated]
TP28  Testpoint  [24mil-plated]
TP29  Testpoint  [24mil-plated]
TP30  Testpoint  [24mil-plated]
U19  SN74AHC1G125DBVR  [SOT235]
U20  TPS3838K33  [SOT23-5]
U21  SN74LVC1G07DBVR  [SOT235]
sheet P16-Master I2C Trig GPIO
D6  LTST-C190EKT  [0603]
D7  LTST-C190GKT  [0603]
J12  TSM-102-01-T-SV  [2POS-2p54mm]
J13  87832-1420  [14POS-2ROWS-2mm]
J14  53261-0471  [4POS-1p25mm]
J15  53261-0471  [4POS-1p25mm]
J16  53261-0471  [4POS-1p25mm]
R123  1k  [0402]
R124  1k  [0402]
R125  1k  [0402]
R126  1k  [0402]
R127  1k  [0402]
R128  4.7k  [0402]
R129  120  [0402]
R130  0  [0402]
R131  0  [0402]
R132  10k  [0402]
R133  120  [0402]
R134  10k  [0402]
R135  10k  [0402]
R136  4.7k  [0402]
R137  10k  [0402]
R138  33  [0402]
R139  1k  [0402]
R140  1k  [0402]
S_TP5  SMD_Testpoint  [5015pad]
S_TP6  SMD_Testpoint  [5015pad]
TP31  Testpoint  [24mil-plated]
sheet P18-Slave Vid DMD io
R143  10k  [0402]
TP32  Testpoint  [24mil-plated]
TP33  Testpoint  [24mil-plated]
sheet P19-Slave JTAG Osc Rst SSP
J17  TMMH-103-01-L-DV  [6POS-2ROWS-2mm]
R144  10k  [0402]
R145  1k  [0402]
R146  33  [0402]
R147  10k  [0402]
TP34  Testpoint  [24mil-plated]
TP35  Testpoint  [24mil-plated]
TP36  Testpoint  [24mil-plated]
TP37  Testpoint  [24mil-plated]
TP38  Testpoint  [24mil-plated]
TP39  Testpoint  [24mil-plated]
TP40  Testpoint  [24mil-plated]
TP41  Testpoint  [24mil-plated]
TP42  Testpoint  [24mil-plated]
TP43  Testpoint  [24mil-plated]
TP44  Testpoint  [24mil-plated]
TP45  Testpoint  [24mil-plated]
TP46  Testpoint  [24mil-plated]
TP47  Testpoint  [24mil-plated]
TP48  Testpoint  [24mil-plated]
sheet P20-Slave Ext Flash Intf
C220  0.1uF  [0402]
C221  0.1uF  [0402]
C371  0.1uF  [0402]
C372  0.1uF  [0402]
C380  0.1uF  [0402]
C381  0.1uF  [0402]
R150  10k  [0402]
R152  10k  [0402]
R153  10k  [0402]
R154  10k  [0402]
R155  22  [0402]
R156  10k  [0402]
R255  10k  [0402]
R256  10k  [0402]
R257  10k  [0402]
R262  10k  [0402]
R263  10k  [0402]
U46  S70GL02GS12FHIV10  [BGA64-BGA_NUMONYX]
U47  SN74ALVC08  [SOIC14-D_TI]
U48  SN74AUP1G14  [SOIC5-DCK_TI]
U53  SN74LVC1G11DBVR  [SOIC6-DBV_TI]
sheet P21-Slave GPIOs
D8  LTST-C190EKT  [0603]
D9  LTST-C190GKT  [0603]
R158  4.7K  [0402]
R159  1K  [0402]
R160  10K  [0603]
R161  0  [0603]
R162  0  [0603]
R163  120  [0402]
R164  10K  [0402]
R165  120  [0402]
TP49  Testpoint  [24mil-plated]
TP50  Testpoint  [24mil-plated]
TP51  Testpoint  [24mil-plated]
TP52  Testpoint  [24mil-plated]
TP53  Testpoint  [24mil-plated]
TP54  Testpoint  [24mil-plated]
TP55  Testpoint  [24mil-plated]
TP56  Testpoint  [24mil-plated]
TP57  Testpoint  [24mil-plated]
TP58  Testpoint  [24mil-plated]
TP59  Testpoint  [24mil-plated]
TP60  Testpoint  [24mil-plated]
TP61  Testpoint  [24mil-plated]
TP62  Testpoint  [24mil-plated]
sheet P22-Slave Pwr/Gnd
U22  DLPC900 (slave)  [516BGA]  (sections A,B,C,D,E,F,G,H,I,J)
sheet P23-DMD Flex Connector
C298  4.7uF  [0603]
C299  0.1uF  [0402]
C300  0.1uF  [0402]
C301  4.7uF  [0603]
C302  0.1uF  [0402]
C303  0.1uF  [0402]
C304  0.1uF  [0402]
C305  0.1uF  [0402]
C306  4.7uF  [0603]
C307  0.1uF  [0402]
C308  0.1uF  [0402]
C309  4.7uF  [0603]
FB25  FBMH1608HM101-T  [0603]
FB26  FBMH1608HM101-T  [0603]
FB27  FBMH1608HM101-T  [0603]
FB28  FBMH1608HM101-T  [0603]
J18  DMD Flex Connector  [150pins]
J19  DMD Flex Connector  [150pins]
R168  DNI  [0402]
R169  DNI  [0402]
R170  1k  [0402]
R171  1k  [0402]
R172  DNI  [0402]
sheet P26-Inout Trigger, LED Driver
C349  0.1uF  [0402]
C350  0.1uF  [0402]
C351  0.1uF  [0402]
C352  0.1uF  [0402]
C353  0.1uF  [0402]
C354  0.1uF  [0402]
C355  0.1uF  [0402]
C356  0.1uF  [0402]
C357  0.1uF  [0402]
C358  0.1uF  [0402]
J22  TSM-103-01-T-SV  [3POS-2p54mm]
J23  0532610671  [6pos_1p25mm]
J24  TSM-103-01-T-SV  [3POS-2p54mm]
J25  TSM-103-01-T-SV  [3POS-2p54mm]
J26  S14B-PHDSS(LF)(SN)(P)  [HDR7X2]
J27  0532610671  [6pos_1p25mm]
J28  TSM-103-01-T-SV  [3POS-2p54mm]
J33  CON6  [CONN6-53261_MOLEX]
R200  10k  [0402]
R201  10k  [0402]
R202  10k  [0402]
R203  10k  [0402]
R204  10k  [0402]
R205  10K  [0402]
R206  10k  [0402]
R207  10K  [0402]
R258  10k  [0402]
R259  10k  [0402]
S_TP15  SMD_Testpoint  [5015pad]
S_TP16  SMD_Testpoint  [5015pad]
S_TP17  SMD_Testpoint  [5015pad]
S_TP18  SMD_Testpoint  [5015pad]
U33  SN74AVC1T45DRLR  [SOT-563]
U34  SN74LVC1G17DBV  [DBV]
U35  SN74AVC1T45DRLR  [SOT-563]
U36  SN74LVC1G17DBV  [DBV]
U37  SN74AVC1T45DRLR  [SOT-563]
U38  SN74AVC1T45DRLR  [SOT-563]
sheet P27-Gen pwrgood posense clk
C359  0.1uF  [0402]
C360  1.0uF  [0402]
C361  0.1uF  [0402]
C362  DNI  [0402]
C363  0.1uF  [0402]
C364  0.1uF  [0402]
D12  LTST-C190GKT  [0603]
FB30  BLM18AG471SN1D  [0603]
FB31  BLM18AG471SN1D  [0603]
J29  TSM-102-01-T-SV  [2POS-2p54mm]
Q2  FDV303N  [SOT-23]
R208  4.7k  [0402]
R209  100  [0603]
R210  DNI  [0402]
R211  10k  [0402]
R212  1k  [0402]
R213  DNI  [0402]
R214  DNI  [0402]
R215  DNI  [0402]
R216  DNI  [0402]
R217  0  [0402]
R218  10k  [0402]
R219  0  [0402]
R220  0  [0402]
R221  0  [0402]
R222  0  [0402]
R223  0  [0402]
R224  0  [0402]
R225  10k  [0402]
R226  10k  [0402]
R227  10k  [0402]
R228  10k  [0402]
R229  10k  [0402]
R230  18  [0603]
R231  18  [0603]
R232  18  [0603]
S_TP19  SMD_Testpoint  [5015pad]
S_TP20  SMD_Testpoint  [5015pad]
S_TP21  SMD_Testpoint  [5015pad]
U39  TL7712ACDR  [8-SOIC]
U40  SN74LV21APWR  [14-TSSOP]
U41  DSC1101CI5-20.0000T  [6PINSxtal]
U42  CDCLVC1103PWR  [TSSOP-8]

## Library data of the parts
U13 U22 = DLPC900_910_datasheet
C144-C147 C220 C221 C299 C300 C302-C305 C307 C308 C361 C363 C364 C371 C372 C380 C381 = CER_0.1UF_16V_10%_X5R_0402: MFG: Samsung; MFG Part Number: CL05A104KO5NNNC
J9 = CONN_HEADER_20POS_2.54mm
J10 J12 J29 = TSM-102-01-T-SV_2POS_.1_SMD
J11 J23 J27 = CONN_HEADER_6POS_1.25MM_R_A_SMD
R97 R105 R119 R128 R136 R158 R208 = 4.7K_OHM_1_10W_5%_0402
R98-R104 R108 R113-R116 R121 R132 R134 R135 R137 R143 R144 R147 R150 R152-R154 R156 R164 R200-R207 R211 R213-R216 R218 R225-R229 R255-R259 R262 R263 = 10K_OHM_1_10W_5%_0402
R106 R107 R109-R112 R117 R118 R161 R162 = 0.0_OHM_1_10W_0603
R120 R122 R138 R146 = 33_OHM_1_16W_5%_0402
SW1 = SWITCH_TACTILE_SPST-NO
TP18-TP62 = Testpoint
U19 = 74AHC1G125
U20 = TPS3838K33
U21 = 74LVC1G07_IC_BUFF_NON-INVERT
D6 D8 = LED_RED_CLEAR_0603
D7 D9 D12 = LED_GREEN_CLEAR_0603
J13 = 87832-1420_14POS_2ROWS_2MM_VERT
J14-J16 = Molex_CONN_HEADER_4POS_1.25MM_R
R123-R127 R139 R140 R145 R159 R168-R172 R212 = 1.0K_OHM_1_16W_5%_0402
R129 R133 R163 R165 = 120_OHM_1_10W_5%_0402
R130 R131 R210 R217 R219-R224 = 0.0_OHM_1_10W_0402
S_TP5 S_TP6 S_TP15-S_TP21 = SMD_Testpoint
J17 = TMMH-103-01-L-DV_6POS_2ROWS_2MM
R155 = 22_OHM_1_10W_1%_0402
U46 = 256MByteParallelFlash: MFG: Cypress
U47 = Quad2inAND: MFG: Texas Instruments; MFG Part Number: SN74ALVC08DR; PART NUMBER: SN74ALVC08DR
U48 = SN74AUP1G14: MFG: Texas Instruments; MFG Part Number: SN74AUP1G14DCKR; PART NUMBER: SN74AUP1G14DCKR
U53 = Single3inAND: MFG: Texas Instruments
R160 = 10K_OHM_1_10W_5%_0603
C298 C301 C306 C309 = CER_4.7UF_16V_20%_X5R_0603
FB25-FB28 = FERRITE_BEAD_100_OHM_2A_0603
J18 J19 = DMD_FLEX_CONNECTOR: MFG Part Number: 8394-001
C349-C359 = CER_0.1UF_25V_10%_X5R_0402
J22 J24 J25 J28 = TSM-103-01-T-SV_3POS_.1_SMD
J26 = LED_CONN_HEADER_14POS_2MM
J33 = CON6_0: Connector, 6 pin; MFG: MOLEX; MFG Part Number: 0532610671; Part Number: 0532610671; SOURCE: DIGI WM7610CT-ND
U33 U35 U37 U38 = SN74AVC1T45_level_translate
U34 U36 = SN74LVC1G17DBV_SCHMIT_TRIG
C360 = CER_1.0UF_16V_10%_X5R_0402: MFG: KEMET; MFG Part Number: C0402C105M4PAC7867
C362 = CER_56PF_50V_5%_NPO_0402
FB30 FB31 = FERRITE_CHIP_470_OHM_500MA_0603
Q2 = FDV303N_MOSFET_N
R209 = 100_OHM_1_10W_5%_0603
R230-R232 = 18_OHM_1_10W_5%_0603
U39 = TL7712A
U40 = SN74LV21A_DUAL_4-IN_AND_GATE
U41 = DSC1101_DSC1121
U42 = CDCLVC1103PWR

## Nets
GND: C144.2 C145.2 C146.2 C147.2 C220.2 C221.2 C298.2 C299.2 C300.2 C301.2 C302.2 C303.2 C304.2 C305.2 C306.2 C307.2 C308.2 C309.2 C349.2 C350.2 C351.2 C352.2 C353.2 C354.2 C355.2 C356.2 C357.2 C358.2 C359.2 C360.2 C361.2 C362.2 C363.2 C364.2 C371.2 C372.2 C380.2 C381.2 D6.1(CATHODE) D7.1(CATHODE) D8.1(CATHODE) D9.1(CATHODE) J9.4 J9.6 J9.8 J9.10 J9.12 J9.14 J9.16 J9.18 J9.20 J10.2 J11.6 J11.7 J11.8 J12.2 J13.12 J13.13 J13.14 J14.4 J15.4 J16.4 J17.6 J18.1A J18.1D J18.2C J18.2F J18.3A J18.3D J18.4C J18.4F J18.5A J18.5D J18.6C J18.6F J18.7A J18.7D J18.8C J18.8F J18.9A J18.9D J18.10C J18.10F J18.11A J18.11D J18.12C J18.12F J18.13D J18.14C J18.14F J18.15A J18.15D J18.16C J18.16F J18.17A J18.17D J18.18C J18.18F J18.19A J18.19D J18.20C J18.20F J18.21A J18.21D J18.22C J18.22F J18.23A J18.23D J18.24C J18.24F J18.25A J18.25D J19.1A J19.1D J19.2C J19.2F J19.3A J19.3D J19.4C J19.4F J19.5A J19.5D J19.6C J19.6F J19.7A J19.7D J19.8C J19.8F J19.9A J19.9D J19.10C J19.10F J19.11A J19.11D J19.12C J19.12F J19.13D J19.14C J19.14F J19.15A J19.15D J19.16C J19.16F J19.17A J19.17D J19.18C J19.18F J19.19A J19.19D J19.20C J19.20F J19.21A J19.21D J19.22C J19.22F J19.23A J19.23D J19.24C J19.24F J19.25A J19.25D J23.3 J23.6 J23.7 J23.8 J26.12(P12) J26.13(P13) J26.14(P14) J27.3 J27.6 J27.7 J27.8 J29.2 J33.6 Q2.S R103.2 R104.2 R119.2 R132.1 R134.2 R135.2 R137.2 R145.2 R147.2 R159.2 R160.2 R164.2 R168.2 R172.2 R201.2 R203.2 R205.2 R207.2 R211.2 R255.2 R256.2 R257.2 R262.2 R263.2 SW1.3 SW1.4 U13.AC6(VPGM) U13.M25(HW_TEST_EN) U19.2(A) U19.3(GND) U20.1(CT) U20.2(GND) U21.1(NC) U21.3(GND) U22.AC6(VPGM) U22.M25(HW_TEST_EN) U33.2(GND) U34.3(GND) U35.2(GND) U36.3(GND) U37.2(GND) U38.2(GND) U39.4(GND) U40.7(GND) U41.3(GND) U42.4(GND) U46.E8(VSS) U46.H2(VSS) U46.H7(VSS) U47.7(GND) U48.3(GND) U53.2(GND) ; also on sheet 1 3 4 5 7 17 18 19 23 25 26 27 28 29
P12V: J18.15F J18.16A J18.16B J19.15F J19.16A J19.16B J26.1(P1) J26.2(P2) J26.3(P3) U39.2(\\~{RESI}N) U39.7(SENSE) U39.8(VCC) ; also on sheet 1 3 7
1P1V_SW_PWRGD: R217.1 ; also on sheet 3 7
1P8V_SW_PWRGD: R221.1 ; also on sheet 7
1P8VA_LDO_PG: R219.1 ; also on sheet 3
3P3V_SW_PWRGD: R223.1 ; also on sheet 7
ASIC_POSENSE: C362.1 R218.2 R220.1 R222.1 S_TP20.1 U40.6(1Y)
BLU_LED_EN: J26.7(P7) R134.1 U13.D24(BLU_LED_EN)
BLU_LED_PWM: J26.10(P10) U13.C20(BLU_LED_PWM)
BUS_SELECT: U13.H23(RESERVED) ; also on sheet 1
BUTTON_RSTZ: J10.1 R105.2 SW1.1 SW1.2 U20.3(\~{_M}R)
CLKBUF_EN: R229.2 U42.2(1G)
CLKBUF_VIN: C363.1 FB31.1 R229.1 U42.6(VDD)
CLKBUFY0: R232.1 U42.3(Y0)
CLKBUFY1: R230.1 U42.8(Y1)
CLKBUFY2: R231.1 U42.5(Y2)
DADADDR0: J18.13E ; also on sheet 19
DADADDR1: J18.13F ; also on sheet 19
DADADDR2: J18.14A ; also on sheet 19
DADADDR3: J18.14B ; also on sheet 19
DADIRQZ: J18.15E R170.2 ; also on sheet 19
DADMODE0: J18.15B ; also on sheet 19
DADMODE1: J18.15C ; also on sheet 19
DADOEZ: J18.12E R171.2 ; also on sheet 19
DADSEL0: J18.14D ; also on sheet 19
DADSEL1: J18.14E ; also on sheet 19
DADSTRB: J18.13C ; also on sheet 19
DASYNC: U13.R22(DA_SYNC_INPUT) U13.T23(FSD12_OUTPUT) U22.R22(DA_SYNC_INPUT)
DMD_P3P3VA: C299.1 FB25.2 J18.1B J18.1C
DMD_P3P3VB: C304.1 FB27.1 J18.25E J18.25F
DMD_P3P3VC: C303.1 FB26.2 J19.1B J19.1C
DMD_P3P3VD: C307.1 FB28.1 J19.25E J19.25F
DMDSPARE0: J18.12D R168.1
DMDSPARE1: J18.11B R169.2 R172.1
EXT_TRIG1_IN_VCC: C350.1 C351.1 J22.2 J23.1 R200.1 U33.1(Vcca) U34.5(VCC)
EXT_TRIG1_OUT_VCC: C356.1 J25.2 J27.1 U37.6(Vccb)
EXT_TRIG2_IN_VCC: C353.1 C354.1 J23.4 J24.2 R202.1 U35.1(Vcca) U36.5(VCC)
EXT_TRIG2_OUT_VCC: C358.1 J27.4 J28.2 U38.6(Vccb)
F_OSC20M: R231.2 ; also on sheet 6
FORCE_SLAVE_RSTZ: J29.1 R225.2 U40.13(2D)
GRN_LED_EN: J26.6(P6) R135.1 U13.C25(GRN_LED_EN)
GRN_LED_PWM: J26.9(P9) U13.B20(GRN_LED_PWM)
HOLDBOOTZ: J12.1 R127.1 U13.F24(HOLD_BOOTZ) U22.F24(HOLD_BOOTZ)
M_DCLKA_N: J18.5C ; also on sheet 19
M_DCLKA_P: J18.5B ; also on sheet 19
M_DCLKB_N: J18.21C ; also on sheet 19
M_DCLKB_P: J18.21B ; also on sheet 19
M_DDA00_N: J18.10E ; also on sheet 19
M_DDA00_P: J18.10D ; also on sheet 19
M_DDA01_N: J18.9C ; also on sheet 19
M_DDA01_P: J18.9B ; also on sheet 19
M_DDA02_N: J18.9F ; also on sheet 19
M_DDA02_P: J18.9E ; also on sheet 19
M_DDA03_N: J18.8B ; also on sheet 19
M_DDA03_P: J18.8A ; also on sheet 19
M_DDA04_N: J18.8E ; also on sheet 19
M_DDA04_P: J18.8D ; also on sheet 19
M_DDA05_N: J18.7C ; also on sheet 19
M_DDA05_P: J18.7B ; also on sheet 19
M_DDA06_N: J18.7F ; also on sheet 19
M_DDA06_P: J18.7E ; also on sheet 19
M_DDA07_N: J18.6B ; also on sheet 19
M_DDA07_P: J18.6A ; also on sheet 19
M_DDA08_N: J18.5F ; also on sheet 19
M_DDA08_P: J18.5E ; also on sheet 19
M_DDA09_N: J18.4B ; also on sheet 19
M_DDA09_P: J18.4A ; also on sheet 19
M_DDA10_N: J18.4E ; also on sheet 19
M_DDA10_P: J18.4D ; also on sheet 19
M_DDA11_N: J18.3C ; also on sheet 19
M_DDA11_P: J18.3B ; also on sheet 19
M_DDA12_N: J18.3F ; also on sheet 19
M_DDA12_P: J18.3E ; also on sheet 19
M_DDA13_N: J18.2B ; also on sheet 19
M_DDA13_P: J18.2A ; also on sheet 19
M_DDA14_N: J18.2E ; also on sheet 19
M_DDA14_P: J18.2D ; also on sheet 19
M_DDA15_N: J18.1F ; also on sheet 19
M_DDA15_P: J18.1E ; also on sheet 19
M_DDB00_N: J18.16E ; also on sheet 19
M_DDB00_P: J18.16D ; also on sheet 19
M_DDB01_N: J18.17C ; also on sheet 19
M_DDB01_P: J18.17B ; also on sheet 19
M_DDB02_N: J18.17F ; also on sheet 19
M_DDB02_P: J18.17E ; also on sheet 19
M_DDB03_N: J18.18B ; also on sheet 19
M_DDB03_P: J18.18A ; also on sheet 19
M_DDB04_N: J18.18E ; also on sheet 19
M_DDB04_P: J18.18D ; also on sheet 19
M_DDB05_N: J18.19C ; also on sheet 19
M_DDB05_P: J18.19B ; also on sheet 19
M_DDB06_N: J18.19F ; also on sheet 19
M_DDB06_P: J18.19E ; also on sheet 19
M_DDB07_N: J18.20B ; also on sheet 19
M_DDB07_P: J18.20A ; also on sheet 19
M_DDB08_N: J18.21F ; also on sheet 19
M_DDB08_P: J18.21E ; also on sheet 19
M_DDB09_N: J18.22B ; also on sheet 19
M_DDB09_P: J18.22A ; also on sheet 19
M_DDB10_N: J18.22E ; also on sheet 19
M_DDB10_P: J18.22D ; also on sheet 19
M_DDB11_N: J18.23C ; also on sheet 19
M_DDB11_P: J18.23B ; also on sheet 19
M_DDB12_N: J18.23F ; also on sheet 19
M_DDB12_P: J18.23E ; also on sheet 19
M_DDB13_N: J18.24B ; also on sheet 19
M_DDB13_P: J18.24A ; also on sheet 19
M_DDB14_N: J18.24E ; also on sheet 19
M_DDB14_P: J18.24D ; also on sheet 19
M_DDB15_N: J18.25C ; also on sheet 19
M_DDB15_P: J18.25B ; also on sheet 19
M_EXT_RSTZ: J18.11F ; also on sheet 18
M_GPIO8_PWM: J13.3 U13.A21(GPIO_PWM_0)
M_GPIO9_PWM: J13.5 U13.B21(GPIO_PWM_1)
M_GPIO10_PWM: J13.7 U13.A22(GPIO_PWM_2)
M_GPIO11_PWM: J13.9 U13.A23(GPIO_PWM_3)
M_GPIO23_AUX2: J13.11 U13.E21(GPIO_8)
M_GPIO43: J13.4 U13.U25(GPIO_4)
M_GPIO44: J13.6 U13.U24(GPIO_5)
M_GPIO49: J13.8 U13.V24(GPIO_6)
M_GPIO50: J13.10 U13.V23(GPIO_7)
M_GPIO66: R136.1 R138.1 U13.J23(TEST_FUNC_1)
M_GPIO67: U13.J24(TEST_FUNC_2) ; also on sheet 6
M_GPIO68: U13.J25(TEST_FUNC_3) ; also on sheet 6
M_GPIO69: U13.J26(TEST_FUNC_4) ; also on sheet 6
M_GPIO70: U13.K22(TEST_FUNC_5) ; also on sheet 6
M_IIC_BUSY: TP31.1 U13.G24(RESERVED)
M_OSC20M: R232.2 ; also on sheet 18
M_PIPESTAT0: TP28.1 U13.C6(RESERVED)
M_PIPESTAT1: TP27.1 U13.B5(RESERVED)
M_PIPESTAT2: TP26.1 U13.A4(RESERVED)
M_POSENSE: R220.2 ; also on sheet 17 18
M_RTCK: R106.1 R120.2
M_RTCK_PIN: R120.1 U13.E4(RTCK)
M_SCL0: J14.1 R124.2 U13.A10(I2C0_SCL) ; also on sheet 1
M_SCL1: J15.1 R126.2 U13.D20(I2C1_SCL) U22.A10(I2C0_SCL) ; also on sheet 1 23 29
M_SCL2: J16.1 R139.2 U13.B22(I2C2_SCL) ; also on sheet 1
M_SCTLA_N: J18.6E ; also on sheet 19
M_SCTLA_P: J18.6D ; also on sheet 19
M_SCTLB_N: J18.20E ; also on sheet 19
M_SCTLB_P: J18.20D ; also on sheet 19
M_SDA0: J14.2 R123.2 U13.B10(I2C0_SDA) ; also on sheet 1
M_SDA1: J15.2 R125.2 U13.E19(I2C1_SDA) U22.B10(I2C0_SDA) ; also on sheet 1 23 29
M_SDA2: J16.2 R140.2 U13.C21(I2C2_SDA) ; also on sheet 1
M_SEQ_AUX6: R130.1 U13.E26(SEQ_AUX6)
M_SEQ_AUX7: R131.1 U13.F26(SEQ_AUX7)
M_SEQ_INT1: R131.2 S_TP6.1 U13.G26(SEQ_INT1)
M_SEQ_INT2: R130.2 S_TP5.1 U13.H26(SEQ_INT2)
M_SEQSYNC_PIN: R122.1 U13.AB9(SEQ_SYNC)
M_STATUS_GRN: R133.1 U13.AB12(HEARTBEAT)
M_STATUS_RED: R129.1 U13.AC11(FAULT_STATUS)
M_TDO1: R111.1 R118.2 U13.N23(TDO1)
M_TDO2: R109.1 R117.1 U13.N22(TDO2)
M_TRACECLK: TP30.1 U13.D7(RESERVED)
M_TRACESYNC: TP29.1 U13.A5(RESERVED)
M_TSTPT0: R116.2 TP25.1 U13.C2(RESERVED)
M_TSTPT1: R115.2 TP24.1 U13.D3(RESERVED)
M_TSTPT2: R114.2 TP23.1 U13.E6(RESERVED)
M_TSTPT3: R113.2 TP22.1 U13.D5(RESERVED)
M_TSTPT4: TP21.1 U13.E7(RESERVED)
M_TSTPT5: TP20.1 U13.C4(RESERVED)
M_TSTPT6: TP19.1 U13.B4(RESERVED)
M_TSTPT7: TP18.1 U13.E8(RESERVED)
M_USB_ENZ: U13.E25(USB_ENZ) ; also on sheet 18
MASTER_ASIC: R128.1 U13.V26(CTRL_MODE_CFG)
OSC20: U41.4(OUT) U42.1(CLK_IN)
OSC_EN: R228.2 U41.1(EN)
OSC_PWR: C364.1 FB30.2 R228.1 U41.6(VDD)
P1P8V: J22.3 J24.3 J25.3 J28.3 ; also on sheet 7 25 27 28
P3P3V: C144.1 C145.1 C146.1 C147.1 C220.1 C221.1 C298.1 C300.1 C301.1 C302.1 C305.1 C306.1 C308.1 C309.1 C349.1 C352.1 C355.1 C357.1 C361.1 C371.1 C372.1 C380.1 C381.1 FB25.1 FB26.1 FB27.2 FB28.2 FB30.1 FB31.2 J9.1 J9.2 J13.1 J13.2 J14.3 J15.3 J16.3 J17.1 J22.1 J24.1 J25.1 J26.11(P11) J28.1 R97.1 R98.1 R99.1 R100.1 R101.1 R102.1 R105.1 R108.1 R113.1 R114.1 R115.1 R116.1 R121.1 R123.1 R124.1 R125.1 R126.1 R127.2 R128.2 R136.2 R139.1 R140.1 R143.1 R144.1 R150.1 R152.1 R153.1 R154.1 R156.1 R158.2 R169.1 R170.1 R171.1 R204.1 R206.1 R208.1 R209.1 R213.1 R214.1 R215.1 R216.1 R218.1 R225.1 R226.1 R227.1 R258.1 R259.1 U19.5(VCC) U20.5(VDD) U21.5(VCC) U33.6(Vccb) U35.6(Vccb) U37.1(Vcca) U38.1(Vcca) U40.14(VCC) U46.D8(VIO) U46.F1(VIO) U46.G5(VCC) U47.14(VCC) U48.5(VCC) U53.5(VCC) ; also on sheet 3 4 7 17 18 19 23 25 27 28 29
PG12V_CT: C360.1 U39.3(CT)
PG12V_REF: C359.1 U39.1(REF)
PG12V_RST: R211.1 U39.6(RESET)
POS_1A_IN: R213.2 R219.2 U40.1(1A)
POS_1B_IN: R214.2 R217.2 U40.2(1B)
POS_1C_IN: R215.2 R221.2 U40.4(1C)
POS_1D_IN: R216.2 R223.2 U40.5(1D)
POWERGOOD: R208.2 R210.1 R212.1 S_TP19.1 U21.4(Y) U39.5(\\~{RESE}T) U40.9(2A) ; also on sheet 18
RED_LED_EN: J26.5(P5) R132.2 U13.B26(RED_LED_EN)
RED_LED_PWM: J26.8(P8) U13.B19(RED_LED_PWM)
RTCK: J9.11 R100.2 R106.2 R107.2
S_3DLR_GPIO78: U22.AF9(RESERVED) ; also on sheet 5
S_CW_PWM: TP34.1 U22.AD8(RESERVED)
S_DADINTZ: R143.2 U22.AC8(DAD_INTZ)
S_DCLKA_N: J19.5C U22.J4(DCKB_N)
S_DCLKA_P: J19.5B U22.J3(DCKB_P)
S_DCLKB_N: J19.21C U22.V3(DCKA_N)
S_DCLKB_P: J19.21B U22.V4(DCKA_P)
S_DDA00_N: J19.10E U22.N2(DDB_N_15)
S_DDA00_P: J19.10D U22.N1(DDB_P_15)
S_DDA01_N: J19.9C U22.N4(DDB_N_14)
S_DDA01_P: J19.9B U22.N3(DDB_P_14)
S_DDA02_N: J19.9F U22.M1(DDB_N_13)
S_DDA02_P: J19.9E U22.M2(DDB_P_13)
S_DDA03_N: J19.8B U22.M4(DDB_N_12)
S_DDA03_P: J19.8A U22.M3(DDB_P_12)
S_DDA04_N: J19.8E U22.L2(DDB_N_11)
S_DDA04_P: J19.8D U22.L1(DDB_P_11)
S_DDA05_N: J19.7C U22.L4(DDB_N_10)
S_DDA05_P: J19.7B U22.L3(DDB_P_10)
S_DDA06_N: J19.7F U22.K2(DDB_N_9)
S_DDA06_P: J19.7E U22.K1(DDB_P_9)
S_DDA07_N: J19.6B U22.K4(DDB_N_8)
S_DDA07_P: J19.6A U22.K3(DDB_P_8)
S_DDA08_N: J19.5F U22.H2(DDB_N_7)
S_DDA08_P: J19.5E U22.H1(DDB_P_7)
S_DDA09_N: J19.4B U22.H4(DDB_N_6)
S_DDA09_P: J19.4A U22.H3(DDB_P_6)
S_DDA10_N: J19.4E U22.G2(DDB_N_5)
S_DDA10_P: J19.4D U22.G1(DDB_P_5)
S_DDA11_N: J19.3C U22.G4(DDB_N_4)
S_DDA11_P: J19.3B U22.G3(DDB_P_4)
S_DDA12_N: J19.3F U22.F2(DDB_N_3)
S_DDA12_P: J19.3E U22.F1(DDB_P_3)
S_DDA13_N: J19.2B U22.F4(DDB_N_2)
S_DDA13_P: J19.2A U22.F3(DDB_P_2)
S_DDA14_N: J19.2E U22.E2(DDB_N_1)
S_DDA14_P: J19.2D U22.E1(DDB_P_1)
S_DDA15_N: J19.1F U22.D2(DDB_N_0)
S_DDA15_P: J19.1E U22.D1(DDB_P_0)
S_DDB00_N: J19.16E U22.P3(DDA_N_15)
S_DDB00_P: J19.16D U22.P4(DDA_P_15)
S_DDB01_N: J19.17C U22.P1(DDA_N_14)
S_DDB01_P: J19.17B U22.P2(DDA_P_14)
S_DDB02_N: J19.17F U22.R3(DDA_N_13)
S_DDB02_P: J19.17E U22.R4(DDA_P_13)
S_DDB03_N: J19.18B U22.R1(DDA_N_12)
S_DDB03_P: J19.18A U22.R2(DDA_P_12)
S_DDB04_N: J19.18E U22.T3(DDA_N_11)
S_DDB04_P: J19.18D U22.T4(DDA_P_11)
S_DDB05_N: J19.19C U22.T1(DDA_N_10)
S_DDB05_P: J19.19B U22.T2(DDA_P_10)
S_DDB06_N: J19.19F U22.U3(DDA_N_9)
S_DDB06_P: J19.19E U22.U4(DDA_P_9)
S_DDB07_N: J19.20B U22.U1(DDA_N_8)
S_DDB07_P: J19.20A U22.U2(DDA_P_8)
S_DDB08_N: J19.21F U22.W3(DDA_N_7)
S_DDB08_P: J19.21E U22.W4(DDA_P_7)
S_DDB09_N: J19.22B U22.W1(DDA_N_6)
S_DDB09_P: J19.22A U22.W2(DDA_P_6)
S_DDB10_N: J19.22E U22.Y1(DDA_N_5)
S_DDB10_P: J19.22D U22.Y2(DDA_P_5)
S_DDB11_N: J19.23C U22.Y3(DDA_N_4)
S_DDB11_P: J19.23B U22.Y4(DDA_P_4)
S_DDB12_N: J19.23F U22.AA1(DDA_N_3)
S_DDB12_P: J19.23E U22.AA2(DDA_P_3)
S_DDB13_N: J19.24B U22.AA3(DDA_N_2)
S_DDB13_P: J19.24A U22.AA4(DDA_P_2)
S_DDB14_N: J19.24E U22.AB1(DDA_N_1)
S_DDB14_P: J19.24D U22.AB2(DDA_P_1)
S_DDB15_N: J19.25C U22.AC1(DDA_N_0)
S_DDB15_P: J19.25B U22.AC2(DDA_P_0)
S_EXTRSTZ: TP35.1 U22.T24(EXT_RSTZ)
S_FLASH0_WP#: R150.2 U46.B4(WP#)
S_FSD12: TP52.1 U22.T23(FSD12_OUTPUT)
S_GPIO04: TP60.1 U22.B19(RED_LED_PWM)
S_GPIO05: TP49.1 U22.B20(GRN_LED_PWM)
S_GPIO06: TP50.1 U22.C20(BLU_LED_PWM)
S_GPIO21_AUX0: TP51.1 U22.E20(TRIG_OUT_1)
S_GPIO22_AUX1: TP53.1 U22.D22(TRIG_OUT_2)
S_GPIO23_AUX2: TP54.1 U22.E21(GPIO_8)
S_GPIO43: TP55.1 U22.U25(GPIO_4)
S_GPIO44: TP56.1 U22.U24(GPIO_5)
S_GPIO49: TP58.1 U22.V24(GPIO_6)
S_GPIO50: TP59.1 U22.V23(GPIO_7)
S_I2C_BUSY: TP57.1 U22.G24(RESERVED)
S_ICTSEN: R145.1 U22.M24(ICTSEN)
S_LMPSTAT: R164.1 U22.AF8(RESERVED)
S_OSC20M: R230.2 U22.M26(MOSCP)
S_P1A0: U22.AE12(P1_A0) ; also on sheet 5
S_P1A1: U22.AF12(P1_A1) ; also on sheet 5
S_P1A2: U22.AF13(P1_A2) ; also on sheet 5
S_P1A3: U22.AF14(P1_A3) ; also on sheet 5
S_P1A4: U22.AC13(P1_A4) ; also on sheet 5
S_P1A5: U22.AD13(P1_A5) ; also on sheet 5
S_P1A6: U22.AE13(P1_A6) ; also on sheet 5
S_P1A7: U22.AE14(P1_A7) ; also on sheet 5
S_P1A8: U22.AE15(P1_A8) ; also on sheet 5
S_P1A9: U22.AD15(P1_A9) ; also on sheet 5
S_P1B0: U22.AD14(P1_B0) ; also on sheet 5
S_P1B1: U22.AC14(P1_B1) ; also on sheet 5
S_P1B2: U22.AF15(P1_B2) ; also on sheet 5
S_P1B3: U22.AF16(P1_B3) ; also on sheet 5
S_P1B4: U22.AE16(P1_B4) ; also on sheet 5
S_P1B5: U22.AD16(P1_B5) ; also on sheet 5
S_P1B6: U22.AC16(P1_B6) ; also on sheet 5
S_P1B7: U22.AC15(P1_B7) ; also on sheet 5
S_P1B8: U22.AB18(P1_B8) ; also on sheet 5
S_P1B9: U22.AF18(P1_B9) ; also on sheet 5
S_P1C0: U22.AE18(P1_C0) ; also on sheet 5
S_P1C1: U22.AC19(P1_C1) ; also on sheet 5
S_P1C2: U22.AF20(P1_C2) ; also on sheet 5
S_P1C3: U22.AF19(P1_C3) ; also on sheet 5
S_P1C4: U22.AE19(P1_C4) ; also on sheet 5
S_P1C5: U22.AD19(P1_C5) ; also on sheet 5
S_P1C6: U22.AF21(P1_C6) ; also on sheet 5
S_P1C7: U22.AE21(P1_C7) ; also on sheet 5
S_P1C8: U22.AE20(P1_C8) ; also on sheet 5
S_P1C9: U22.AD20(P1_C9) ; also on sheet 5
S_P1DATEN: TP32.1 U22.AF22(P_DATAEN1) ; also on sheet 5
S_P1HS: U22.AD21(P1_HSYNC) ; also on sheet 5
S_P1VS: TP33.1 U22.AC20(P1_VSYNC) ; also on sheet 5
S_P2A0: U22.AB19(P2_A0) ; also on sheet 5
S_P2A1: U22.AE23(P2_A1) ; also on sheet 5
S_P2A2: U22.AD22(P2_A2) ; also on sheet 6
S_P2A3: U22.AC21(P2_A3) ; also on sheet 6
S_P2A4: U22.AB20(P2_A4) ; also on sheet 6
S_P2A5: U22.AD23(P2_A5) ; also on sheet 6
S_P2A6: U22.AC22(P2_A6) ; also on sheet 6
S_P2A7: U22.AB21(P2_A7) ; also on sheet 6
S_P2A8: U22.AD25(P2_A8) ; also on sheet 6
S_P2A9: U22.AD26(P2_A9) ; also on sheet 6
S_P2B0: U22.AC24(P2_B0) ; also on sheet 6
S_P2B1: U22.AC25(P2_B1) ; also on sheet 6
S_P2B2: U22.AB23(P2_B2) ; also on sheet 6
S_P2B3: U22.AC26(P2_B3) ; also on sheet 6
S_P2B4: U22.AB24(P2_B4) ; also on sheet 6
S_P2B5: U22.AA22(P2_B5) ; also on sheet 6
S_P2B6: U22.AB25(P2_B6) ; also on sheet 6
S_P2B7: U22.AA23(P2_B7) ; also on sheet 6
S_P2B8: U22.AB26(P2_B8) ; also on sheet 6
S_P2B9: U22.Y22(P2_B9) ; also on sheet 6
S_P2C0: U22.AA24(P2_C0) ; also on sheet 6
S_P2C1: U22.AA25(P2_C1) ; also on sheet 6
S_P2C2: U22.AA26(P2_C2) ; also on sheet 6
S_P2C3: U22.W22(P2_C3) ; also on sheet 6
S_P2C4: U22.Y23(P2_C4) ; also on sheet 6
S_P2C5: U22.Y24(P2_C5) ; also on sheet 6
S_P2C6: U22.Y25(P2_C6) ; also on sheet 6
S_P2C7: U22.Y26(P2_C7) ; also on sheet 6
S_P2C8: U22.V22(P2_C8) ; also on sheet 6
S_P2C9: U22.W23(P2_C9) ; also on sheet 6
S_PCLK1: U22.AE22(P_CLK1) ; also on sheet 5
S_PGOOD: R224.1 U40.8(2Y)
S_PIPESTAT0: TP46.1 U22.C6(RESERVED)
S_PIPESTAT1: TP45.1 U22.B5(RESERVED)
S_PIPESTAT2: TP44.1 U22.A4(RESERVED)
S_PM_ADDR_GPIO45: R257.1 U22.U23(GPIO_45_PM_ADDR) U47.5(2B)
S_PM_ADDR_GPIO46: R256.1 U22.T22(GPIO_46_PM_ADDR) U47.2(1B)
S_PM_ADDR_GPIO60: R255.1 U22.H22(GPIO_60_PM_ADDR) U47.9(3A)
S_PM_CEZ: U46.F2(CE#) U53.4(Y)
S_PM_CSZ0: R154.2 U22.D13(PM_CSZ_0) U53.1(A)
S_PM_CSZ1: R153.2 U22.E12(PM_CSZ_1) U47.1(1A) U47.4(2A) U47.10(3B) U53.3(B)
S_PM_CSZ2: R152.2 U22.A13(PM_CSZ_2) U48.2(A) U53.6(C)
S_PM_OEZ: U22.C13(PM_OEZ) U46.G2(OE#)
S_PM_WEZ: R155.1 U46.A5(WE#)
S_PMADDR00: U22.C7(PM_ADDR_00) U46.E2(A0)
S_PMADDR01: U22.A7(PM_ADDR_01) U46.D2(A1)
S_PMADDR02: U22.B7(PM_ADDR_02) U46.C2(A2)
S_PMADDR03: U22.C8(PM_ADDR_03) U46.A2(A3)
S_PMADDR04: U22.D8(PM_ADDR_04) U46.B2(A4)
S_PMADDR05: U22.A8(PM_ADDR_05) U46.D3(A5)
S_PMADDR06: U22.B8(PM_ADDR_06) U46.C3(A6)
S_PMADDR07: U22.C9(PM_ADDR_07) U46.A3(A7)
S_PMADDR08: U22.D9(PM_ADDR_08) U46.B6(A8)
S_PMADDR09: U22.E9(PM_ADDR_09) U46.A6(A9)
S_PMADDR10: U22.A9(PM_ADDR_10) U46.C6(A10)
S_PMADDR11: U22.B9(PM_ADDR_11) U46.D6(A11)
S_PMADDR12: U22.C10(PM_ADDR_12) U46.B7(A12)
S_PMADDR13: U22.D10(PM_ADDR_13) U46.A7(A13)
S_PMADDR14: U22.E10(PM_ADDR_14) U46.C7(A14)
S_PMADDR15: U22.C11(PM_ADDR_15) U46.D7(A15)
S_PMADDR16: U22.D11(PM_ADDR_16) U46.E7(A16)
S_PMADDR17: U22.A11(PM_ADDR_17) U46.B3(A17)
S_PMADDR18: U22.B11(PM_ADDR_18) U46.C4(A18)
S_PMADDR19: U22.C12(PM_ADDR_19) U46.D5(A19)
S_PMADDR20: U22.D12(PM_ADDR_20) U46.D4(A20)
S_PMADDR21: R262.1 U22.E11(PM_ADDR_21) U46.C5(A21)
S_PMADDR22: R263.1 U22.A12(PM_ADDR_22) U46.B8(A22)
S_PMADDR23: U46.C8(A23) U48.4(Y)
S_PMADDR24: U46.F8(A24) U47.6(2Y)
S_PMADDR25: U46.G8(A25) U47.3(1Y)
S_PMADDR26: U46.B1(A26) U47.8(3Y)
S_PMDATA_00: U22.B13(PM_DATA_00) U46.E3(DQ0)
S_PMDATA_01: U22.C14(PM_DATA_01) U46.H3(DQ1)
S_PMDATA_02: U22.D14(PM_DATA_02) U46.E4(DQ2)
S_PMDATA_03: U22.E13(PM_DATA_03) U46.H4(DQ3)
S_PMDATA_04: U22.A14(PM_DATA_04) U46.H5(DQ4)
S_PMDATA_05: U22.B14(PM_DATA_05) U46.E5(DQ5)
S_PMDATA_06: U22.C15(PM_DATA_06) U46.H6(DQ6)
S_PMDATA_07: U22.D15(PM_DATA_07) U46.E6(DQ7)
S_PMDATA_08: U22.E14(PM_DATA_08) U46.F3(DQ8)
S_PMDATA_09: U22.C16(PM_DATA_09) U46.G3(DQ9)
S_PMDATA_10: U22.D16(PM_DATA_10) U46.F4(DQ10)
S_PMDATA_11: U22.B15(PM_DATA_11) U46.G4(DQ11)
S_PMDATA_12: U22.A15(PM_DATA_12) U46.F5(DQ12)
S_PMDATA_13: U22.A16(PM_DATA_13) U46.G6(DQ13)
S_PMDATA_14: U22.B16(PM_DATA_14) U46.F6(DQ14)
S_PMDATA_15: U22.C17(PM_DATA_15) U46.G7(DQ15)
S_PMDINTZ: R144.2 U22.AE8(RESERVED)
S_PMWEZ_PIN: R155.2 U22.B12(PM_WEZ)
S_POSENSE: R222.2 U22.P22(POSENSE) U46.B5(RESET#)
S_POWERGOOD: R210.2 R224.2 S_TP21.1 U22.T26(PWRGOOD)
S_RTCK: R107.1 R146.2
S_RTCK_OUT: R146.1 U22.E4(RTCK)
S_SCTLA_N: J19.6E U22.J2(SCB_N)
S_SCTLA_P: J19.6D U22.J1(SCB_P)
S_SCTLB_N: J19.20E U22.V1(SCA_N)
S_SCTLB_P: J19.20D U22.V2(SCA_P)
S_SEQ_AUX6: R161.1 U22.E26(SEQ_AUX6)
S_SEQ_AUX7: R162.1 U22.F26(SEQ_AUX7)
S_SEQ_INT1: R162.2 TP61.1 U22.G26(SEQ_INT1)
S_SEQ_INT2: R161.2 TP62.1 U22.H26(SEQ_INT2)
S_STATUS_GRN: R165.1 U22.AB12(HEARTBEAT)
S_STATUS_RED: R163.1 U22.AC11(FAULT_STATUS)
S_TDI: R117.2 R118.1 U22.N25(TDI)
S_TDO1: R112.1 U22.N23(TDO1)
S_TDO2: R110.1 U22.N22(TDO2)
S_TRACECLK: TP48.1 U22.D7(RESERVED)
S_TRACESYNC: TP47.1 U22.A5(RESERVED)
S_TSTPT0: TP43.1 U22.C2(RESERVED)
S_TSTPT1: TP42.1 U22.D3(RESERVED)
S_TSTPT2: TP41.1 U22.E6(RESERVED)
S_TSTPT3: TP40.1 U22.D5(RESERVED)
S_TSTPT4: TP39.1 U22.E7(RESERVED)
S_TSTPT5: TP38.1 U22.C4(RESERVED)
S_TSTPT6: TP37.1 U22.B4(RESERVED)
S_TSTPT7: TP36.1 U22.E8(RESERVED)
S_UART0_CTSZ: J17.4 R147.1 U22.AE2(UART0_CTSZ)
S_UART0_RTSZ: J17.5 U22.AD2(UART0_RTSZ)
S_UART0_RXD: J17.3 U22.AD1(UART0_RXD)
S_UART0_TXD: J17.2 U22.AB3(UART0_TXD)
SEQ_SYNC: R121.2 R122.2 U22.AB9(SEQ_SYNC)
SFLASH_RYBYZ: R156.2 U46.A4(RY/BY#)
SLAVE_ASIC: R159.1 U22.V26(CTRL_MODE_CFG)
SLAVE_INT: R160.1 U13.V25(SLV_CTRL_PRST) U22.V25(SLV_CTRL_PRST)
SPGAND_2B_IN: R227.2 U40.10(2B)
SPGAND_2C_IN: R226.2 U40.12(2C)
SRSTZ: J9.15 R108.2 U20.4(\~{_RESE}T) U21.2(A)
SSP0_CLK: J18.10B U22.AD4(SSP0_CLK) ; also on sheet 6 18
SSP0_CSZ0_DAD1: J18.12A ; also on sheet 18
SSP0_CSZ1_DMD: J18.11C ; also on sheet 18
SSP0_CSZ4_SLAVE: R158.1 U13.U26(SSP0_CSZ4_SLV) U22.U26(SSP0_CSZ4_SLV)
SSP0_CSZ5_DAD2: J18.12B R138.2
SSP0_RXD_S2M: J18.11E U22.AB7(SSP0_TXD) ; also on sheet 6 18
SSP0_TXD_M2S: J18.10A U22.AD5(SSP0_RXD) ; also on sheet 6 18
SSP1_CLK: J33.1 ; also on sheet 18
SSP1_CSZ_0: J33.4 R258.2 ; also on sheet 18
SSP1_CSZ_1: J33.5 R259.2 ; also on sheet 18
SSP1_DIN: J33.2 ; also on sheet 18
SSP1_DO: J33.3 ; also on sheet 18
TCK: J9.9 J11.5 R102.2 R104.1 U13.N24(TCK) U22.N24(TCK)
TDI: J9.5 J11.2 R98.2 U13.N25(TDI)
TDO1: J11.4 R111.2 R112.2
TDO2: J9.13 R101.2 R109.2 R110.2
TMS1: J11.3 U13.P25(TMS1) U22.P25(TMS1)
TMS2: J9.7 R99.2 U13.P26(TMS2) U22.P26(TMS2)
TRIG1_IN_CON: J23.2 U34.2
TRIG1_IN_T: U33.3(A) U34.4
TRIG1_OUT_CON: J27.2 U37.4(B)
TRIG2_IN_CON: J23.5 U36.2
TRIG2_IN_T: U35.3(A) U36.4
TRIG2_OUT_CON: J27.5 U38.4(B)
TRIGGER_IN1: R201.1 S_TP15.1 U22.AF7(TRIG_IN_1) U33.4(B) ; also on sheet 18
TRIGGER_IN2: R203.1 S_TP16.1 U13.H25(TRIG_IN_2) U22.H25(TRIG_IN_2) U35.4(B)
TRIGGER_OUT_AUX0: R205.1 S_TP17.1 U13.E20(TRIG_OUT_1) U37.3(A)
TRIGGER_OUT_AUX1: R207.1 S_TP18.1 U13.D22(TRIG_OUT_2) U38.3(A)
TRSTZ: R97.2 U13.M23(TRSTZ) U19.4(Y) U22.M23(TRSTZ)
TRSTZ_IN: J9.3 J11.1 R103.1 U19.1(~{OE})
N20224398: R119.1 U13.M24(ICTSEN)
N20250700: R137.1 U13.AF8(RESERVED)
N20263361: D6.2(ANODE) R129.2
N20271735: D7.2(ANODE) R133.2
N20345555: D9.2(ANODE) R165.2
N20345600: D8.2(ANODE) R163.2
N20518299: R202.2 U35.5(DIR)
N20519329: R200.2 U33.5(DIR)
N20522932: R204.2 U37.5(DIR)
N20523509: R206.2 U38.5(DIR)
N21371449: D12.2(ANODE) R209.2
N21371451: Q2.G R212.2
N21371492: D12.1(CATHODE) Q2.D

Not connected (* = marked no-connect by the designer): J9 17* 19*; J18 13A* 13B*; J19 10A* 10B* 11B* 11C* 11E* 11F* 12A* 12B* 12D* 12E* 13A* 13B* 13C* 13E* 13F* 14A* 14B* 14D* 14E* 15B* 15C* 15E*; J26 4(P4)*; J33 7* 8*; U13 A19(RESERVED)* A20(RESERVED)* AB11(RESERVED)* AC9(RESERVED)* AC10(RESERVED)* AD10(RESERVED)* AE10(RESERVED)* AF10(RESERVED)* B24(RESERVED)* C19(RESERVED)* C23(RESERVED)* C26(RESERVED)* D19(RESERVED)* D21(RESERVED)* E3(RESERVED)* E18(RESERVED)* E23(RESERVED)* G22(RESERVED)* G25(RESERVED)* H24(RESERVED)* J22(RESERVED)* K23(RESERVED)* K24(RESERVED)*; U22 A6(PM_BLSZ_0)* A19(RESERVED)* A20(RESERVED)* A21(GPIO_PWM_0)* A22(GPIO_PWM_2)* A23(GPIO_PWM_3)* AB4(RESERVED)* AB6(SSP0_CSZ_1)* AB8(DADADDR_0)* AB10(RESERVED)* AB11(RESERVED)* AB13(AFE_IRQ)* AC3(SSP0_CSZ_2)* AC5(SSP0_CSZ_0)* AC7(DADSEL_0)* AC9(RESERVED)* AC10(RESERVED)* AC12(AFE_ARSTZ)* AD6(DADADDR_3)* AD7(DADMODE_1)* AD9(RESERVED)* AD10(RESERVED)* AD11(RESERVED)* AD12(RESERVED)* AE4(DADSEL_1)* AE5(DADADDR_2)* AE6(DADMODE_0)* AE7(DADOEZ)* AE9(RESERVED)* AE10(RESERVED)* AE11(RESERVED)* AF4(DADADDR_1)* AF5(DADSTRB)* AF6(OCLKA)* AF10(RESERVED)* AF11(RESERVED)* AF23(P_CLK3)* B6(PM_BLSZ_1)* B21(GPIO_PWM_1)* B22(I2C2_SCL)* B23(RESERVED)* B24(RESERVED)* B26(RED_LED_EN)* C5(USB_DAT_N)* C19(RESERVED)* C21(I2C2_SDA)* C22(RESERVED)* C23(RESERVED)* C25(GRN_LED_EN)* C26(RESERVED)* D6(USB_DAT_P)* D19(RESERVED)* D20(I2C1_SCL)* D21(RESERVED)* D24(BLU_LED_EN)* D25(RESERVED)* D26(RESERVED)* E3(RESERVED)* E18(RESERVED)* E19(I2C1_SDA)* E23(RESERVED)* E24(RESERVED)* E25(USB_ENZ)* F22(RESERVED)* F23(RESERVED)* F25(RESERVED)* G22(RESERVED)* G23(RESERVED)* G25(RESERVED)* H23(RESERVED)* H24(RESERVED)* J22(RESERVED)* J23(TEST_FUNC_1)* J24(TEST_FUNC_2)* J25(TEST_FUNC_3)* J26(TEST_FUNC_4)* K22(TEST_FUNC_5)* K23(RESERVED)* K24(RESERVED)* N26(MOSCN)* T25(CTRL_ARSTZ)* U22(P2_VSYNC)* W24(P_DATAEN2)* W25(P_CLK2)* W26(P2_HSYNC)*; U34 1*; U36 1*; U40 3(NC)* 11(NC)*; U41 2(NC2)* 5(NC5)*; U42 7(NC7)*; U46 A1(NC)* A8(NC)* C1(NC)* D1(NC)* E1(DNU)* F7(RFU)* G1(RFU)* H1(NC)* H8(NC)*; U47 11(4Y)* 12(4A)* 13(4B)*; U48 1(NC)*

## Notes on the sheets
sheet 8
- Master DMD Flex
- Slave DMD Flex
- DMD Master/Slave Flex Connector
- TI Information
           Selective Disclosure
  Property of Texas Instruments Only
sheet 9
- Slave Controller Flash Interface
- TI Information
           Selective Disclosure
  Property of Texas Instruments Only
sheet 10
- Must have pulldown on Slave
  pin V26 for normal operation.
  Pin V25 of Master and Slave
  Controller must be tied
  together for proper operation
- Must connect pin
  E26 to H26, and
  pin F26 to G26 for
  normal operation
- TI Information
           Selective Disclosure
  Property of Texas Instruments Only
- Slave Controller I2C, GPIOs
sheet 11
- UART debug message port,
  not needed for production
- Slave Controller Reset, OSC, JTAG, UART0, SSP Port
- TI Information
           Selective Disclosure
  Property of Texas Instruments Only
sheet 12
- Swap A/B channel, and buses' bit order for
  ease of routing to flex connector
- Slave Controller Video Input, DMD Output
- TI Information
           Selective Disclosure
  Property of Texas Instruments Only
sheet 13
- Use external voltage reference
  or on board 3.3V/1.8V supply
- Input Trigger 1 to controller
- Input Trigger Port
- Input Trigger 2 to controller
- Use external voltage reference
  or on board 3.3V/1.8V supply
- Output Trigger Port
- To LED driver board
- Input/Output Trigger and LED Driver Interface
- TI Information
           Selective Disclosure
  Property of Texas Instruments Only
sheet 14
- Per controller spec (Fig. 3), POWERGOOD has no
  impact on operation for 60ms after rising
  edge of POSENSE. In other words, during
  power up, controller will ignore the state of PG
  until the internal PLL is locked (require up to 60ms).
  Controller will then sample the PG input to begin
  normal operation.
  During power down, POSENSE has to remain
  valid high for at least 500us after PG is deasserted
  to allow controller to complete the DMD parking procedure.
  The 500+ uF input caps on 12V would ensure
  the power monitor to trip at ~11V to deassert PG
  while keeping regulators operational to maintain
  POSENSE for > 500us.
- D
- FDV303N
- G
- S
- Install jumper to hold Slave Controller
  in reset for Single Controller operation
- Powergood, POSENSE, Conroller Clocks
- TI Information
           Selective Disclosure
  Property of Texas Instruments Only
sheet 15
- Install jumper to
  hold controllers  in
  boot mode
- Must have pullup on
  Master pin V26 for
  normal operation.
  Pin V25 of Master and
  Slave Controller must
  be tied together for
  proper operation
- GPIO User Connector
- Must connect pin
  E26 to H26, and
  pin F26 to G26 for
  normal operation
- I2C Port 0
- I2C Port 1
- I2C Port 2
- Master Controller I2C, LED driver interface, In/Out Triggers and GPIOs
- TI Information
           Selective Disclosure
  Property of Texas Instruments Only
sheet 16
- ARM Multi-ICE debug port
- Install R106 only if slave
  controller is not populated
  for single controller
  operation
- Install jumper to hold controllers in reset
- Install R109 only if slave
  controller is not populated
  for single controller
  operation
- Pullup on open-drain signal
  POWERGOOD found on page 27
- Install R111 only if slave
  controller is not populated
  for single controller
  operation
- Install R118 if using the JTAG boundary scan
  port to program the external flash memory with
  TI GUI's flash downloader. R117 is installed only
  if using the ARM Realview ICE debugger HW.
- SEQ_SYNC used to
  synchronize PWM sequences
  in multi-controller system
- JTAG Boundary scan port may be
  used to download flash image using
  USB-to-JTAG FTDI adapter board
- Master Controller Multi-ICE Port
- TI Information
           Selective Disclosure
  Property of Texas Instruments Only
